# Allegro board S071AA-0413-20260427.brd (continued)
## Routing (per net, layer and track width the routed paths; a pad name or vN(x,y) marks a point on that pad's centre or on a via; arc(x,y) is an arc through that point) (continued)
GND12A_SCG: length 13.7
  L11_DPS w0.076: v2(149.12,210.23) 149.12,210.67 149.92,211.47 156.28,211.47
  L11_DPS w0.203: 156.28,211.47 156.45,211.47 156.66,211.67 v1(160.56,211.67)
  BOTTOM w0.152: SH6.1 160.56,211.68 v1(160.56,211.67)
  vias: v1(120.92,288.29) v1(120.92,283.21) v1(121.7,279.15) v1(129.28,279.15) v1(130.06,288.29) v1(130.06,283.21) v1(141.54,266.67) v1(141.54,263.88) v1(174.34,250.56) v1(174.34,247.77) v1(188.49,214.19) v1(188.49,211.4) v1(191.21,236.22) v1(191.21,233.42)
GND33A_ADC12: length 840.7
  L02_DGND w0.203: K39.6 121.78,141.22 ; K39.6 120.67,140.11 ; K39.6 120.67,142.34 ; K39.6 119.55,141.22 ; 150.03,164.34 K42.6 ; K42.6 151.15,163.22 ; K42.6 151.15,165.46 ; K42.6 152.26,164.34 ; 113.05,140.11 K35.6 ; K35.6 111.93,141.22 ; K35.6 113.05,142.34 ; K35.6 114.16,141.22 ; 128.29,163.22 K41.6 ; K41.6 129.4,164.34 ; K41.6 128.29,165.46 ; K41.6 127.17,164.34 ; K43.7 129.4,153.92 ; K43.7 128.29,155.04 ; K43.7 127.17,153.92 ; K43.7 128.29,152.81 ; K38.7 143.53,178.16 ; K38.7 144.64,177.04 ; K38.7 143.53,175.92 ; K38.7 142.41,177.04 ; K37.6 121.78,164.34 ; K37.6 120.67,163.22 ; K37.6 119.55,164.34 ; K37.6 120.67,165.46 ; 128.29,175.92 K41.7 ; K41.7 128.29,178.16 ; K41.7 129.4,177.04 ; K41.7 127.17,177.04 ; K43.6 129.4,141.22 ; K43.6 128.29,142.34 ; K43.6 128.29,140.11 ; K43.6 127.17,141.22 ; K36.7 135.91,154.79 ; K36.7 137.02,153.67 ; K36.7 135.91,152.55 ; K36.7 134.79,153.67 ; K34.7 135.91,178.16 ; K34.7 134.79,177.04 ; K34.7 137.02,177.04 ; K34.7 135.91,175.92 ; K44.6 151.15,142.09 ; K44.6 151.15,139.85 ; K44.6 152.26,140.97 ; K44.6 150.03,140.97 ; 119.55,177.04 K37.7 ; K37.7 120.67,178.16 ; K37.7 120.67,175.92 ; K37.7 121.78,177.04 ; 150.03,153.67 K44.7 ; K44.7 151.15,154.79 ; K44.7 151.15,152.55 ; K44.7 152.26,153.67 ; 142.41,140.97 K40.6 ; K40.6 144.64,140.97 ; K40.6 143.53,139.85 ; K40.6 143.53,142.09 ; 113.05,163.22 K33.6 ; K33.6 111.93,164.34 ; K33.6 114.16,164.34 ; K33.6 113.05,165.46 ; K42.7 152.26,177.04 ; K42.7 151.15,175.92 ; K42.7 151.15,178.16 ; K42.7 150.03,177.04 ; K33.7 113.05,178.16 ; K33.7 111.93,177.04 ; K33.7 113.05,175.92 ; K33.7 114.16,177.04 ; K35.7 114.16,153.92 ; K35.7 113.05,155.04 ; K35.7 113.05,152.81 ; K35.7 111.93,153.92 ; 119.55,153.92 K39.7 ; K39.7 121.78,153.92 ; K39.7 120.67,155.04 ; K39.7 120.67,152.81 ; 143.53,152.55 K40.7 ; K40.7 142.41,153.67 ; K40.7 144.64,153.67 ; K40.7 143.53,154.79 ; 134.79,164.34 K34.6 ; K34.6 135.91,163.22 ; K34.6 137.02,164.34 ; K34.6 135.91,165.46 ; 143.53,163.22 K38.6 ; K38.6 142.41,164.34 ; K38.6 144.64,164.34 ; K38.6 143.53,165.46 ; 135.91,139.85 K36.6 ; K36.6 135.91,142.09 ; K36.6 137.02,140.97 ; K36.6 134.79,140.97
  L04_DGND w0.203: K33.6 113.05,165.46 ; K33.6 113.05,163.22 ; K33.6 114.16,164.34 ; K33.6 111.93,164.34 ; K39.6 120.67,142.34 ; K39.6 121.78,141.22 ; K39.6 119.55,141.22 ; K39.6 120.67,140.11 ; 128.29,163.22 K41.6 ; K41.6 127.17,164.34 ; K41.6 128.29,165.46 ; K41.6 129.4,164.34 ; 128.29,175.92 K41.7 ; K41.7 129.4,177.04 ; K41.7 127.17,177.04 ; K41.7 128.29,178.16 ; K35.7 113.05,155.04 ; K35.7 111.93,153.92 ; K35.7 114.16,153.92 ; K35.7 113.05,152.81 ; K43.7 128.29,155.04 ; K43.7 127.17,153.92 ; K43.7 129.4,153.92 ; K43.7 128.29,152.81 ; K38.7 143.53,178.16 ; K38.7 142.41,177.04 ; K38.7 143.53,175.92 ; K38.7 144.64,177.04 ; K38.6 144.64,164.34 ; K38.6 143.53,165.46 ; K38.6 142.41,164.34 ; K38.6 143.53,163.22 ; K39.7 121.78,153.92 ; K39.7 120.67,152.81 ; K39.7 119.55,153.92 ; K39.7 120.67,155.04 ; K35.6 113.05,142.34 ; K35.6 111.93,141.22 ; K35.6 113.05,140.11 ; K35.6 114.16,141.22 ; K43.6 129.4,141.22 ; K43.6 127.17,141.22 ; K43.6 128.29,140.11 ; K43.6 128.29,142.34 ; K44.6 152.26,140.97 ; K44.6 151.15,139.85 ; K44.6 150.03,140.97 ; K44.6 151.15,142.09 ; K36.7 135.91,154.79 ; K36.7 137.02,153.67 ; K36.7 134.79,153.67 ; K36.7 135.91,152.55 ; 120.67,175.92 K37.7 ; K37.7 121.78,177.04 ; K37.7 119.55,177.04 ; K37.7 120.67,178.16 ; K44.7 151.15,154.79 ; K44.7 151.15,152.55 ; K44.7 150.03,153.67 ; K44.7 152.26,153.67 ; 142.41,140.97 K40.6 ; K40.6 143.53,139.85 ; K40.6 144.64,140.97 ; K40.6 143.53,142.09 ; 150.03,164.34 K42.6 ; K42.6 151.15,165.46 ; K42.6 151.15,163.22 ; K42.6 152.26,164.34 ; K34.7 137.02,177.04 ; K34.7 134.79,177.04 ; K34.7 135.91,175.92 ; K34.7 135.91,178.16 ; K33.7 113.05,178.16 ; K33.7 113.05,175.92 ; K33.7 114.16,177.04 ; K33.7 111.93,177.04 ; 119.55,164.34 K37.6 ; K37.6 121.78,164.34 ; K37.6 120.67,165.46 ; K37.6 120.67,163.22 ; 135.91,163.22 K34.6 ; K34.6 137.02,164.34 ; K34.6 134.79,164.34 ; K34.6 135.91,165.46 ; K42.7 152.26,177.04 ; K42.7 151.15,178.16 ; K42.7 150.03,177.04 ; K42.7 151.15,175.92 ; K36.6 135.91,142.09 ; K36.6 135.91,139.85 ; K36.6 137.02,140.97 ; K36.6 134.79,140.97 ; 143.53,152.55 K40.7 ; K40.7 142.41,153.67 ; K40.7 144.64,153.67 ; K40.7 143.53,154.79
  L06_DGND w0.203: K44.6 152.26,140.97 ; K44.6 150.03,140.97 ; K44.6 151.15,139.85 ; K44.6 151.15,142.09 ; K34.6 135.91,165.46 ; K34.6 137.02,164.34 ; K34.6 135.91,163.22 ; K34.6 134.79,164.34 ; 120.67,163.22 K37.6 ; K37.6 119.55,164.34 ; K37.6 121.78,164.34 ; K37.6 120.67,165.46 ; K39.6 120.67,142.34 ; K39.6 121.78,141.22 ; K39.6 120.67,140.11 ; K39.6 119.55,141.22 ; K38.6 143.53,165.46 ; K38.6 142.41,164.34 ; K38.6 143.53,163.22 ; K38.6 144.64,164.34 ; K36.7 135.91,154.79 ; K36.7 137.02,153.67 ; K36.7 135.91,152.55 ; K36.7 134.79,153.67 ; 113.05,152.81 K35.7 ; K35.7 114.16,153.92 ; K35.7 111.93,153.92 ; K35.7 113.05,155.04 ; 143.53,152.55 K40.7 ; K40.7 142.41,153.67 ; K40.7 144.64,153.67 ; K40.7 143.53,154.79 ; 128.29,163.22 K41.6 ; K41.6 127.17,164.34 ; K41.6 128.29,165.46 ; K41.6 129.4,164.34 ; K39.7 121.78,153.92 ; K39.7 120.67,155.04 ; K39.7 119.55,153.92 ; K39.7 120.67,152.81 ; K40.6 143.53,142.09 ; K40.6 143.53,139.85 ; K40.6 144.64,140.97 ; K40.6 142.41,140.97 ; K36.6 137.02,140.97 ; K36.6 135.91,139.85 ; K36.6 135.91,142.09 ; K36.6 134.79,140.97 ; K33.6 113.05,165.46 ; K33.6 113.05,163.22 ; K33.6 111.93,164.34 ; K33.6 114.16,164.34 ; K44.7 152.26,153.67 ; K44.7 151.15,154.79 ; K44.7 150.03,153.67 ; K44.7 151.15,152.55 ; 150.03,177.04 K42.7 ; K42.7 151.15,175.92 ; K42.7 151.15,178.16 ; K42.7 152.26,177.04 ; 135.91,175.92 K34.7 ; K34.7 135.91,178.16 ; K34.7 137.02,177.04 ; K34.7 134.79,177.04 ; K35.6 114.16,141.22 ; K35.6 113.05,142.34 ; K35.6 113.05,140.11 ; K35.6 111.93,141.22 ; 127.17,141.22 K43.6 ; K43.6 128.29,140.11 ; K43.6 128.29,142.34 ; K43.6 129.4,141.22 ; K42.6 151.15,165.46 ; K42.6 152.26,164.34 ; K42.6 151.15,163.22 ; K42.6 150.03,164.34 ; K33.7 113.05,178.16 ; K33.7 111.93,177.04 ; K33.7 113.05,175.92 ; K33.7 114.16,177.04 ; K43.7 128.29,155.04 ; K43.7 127.17,153.92 ; K43.7 128.29,152.81 ; K43.7 129.4,153.92 ; 119.55,177.04 K37.7 ; K37.7 120.67,175.92 ; K37.7 121.78,177.04 ; K37.7 120.67,178.16 ; K38.7 144.64,177.04 ; K38.7 143.53,178.16 ; K38.7 143.53,175.92 ; K38.7 142.41,177.04 ; K41.7 129.4,177.04 ; K41.7 127.17,177.04 ; K41.7 128.29,175.92 ; K41.7 128.29,178.16
  L08_DGND w0.203: 143.53,152.55 K40.7 ; K40.7 142.41,153.67 ; K40.7 143.53,154.79 ; K40.7 144.64,153.67 ; 143.53,139.85 K40.6 ; K40.6 143.53,142.09 ; K40.6 144.64,140.97 ; K40.6 142.41,140.97 ; 127.17,141.22 K43.6 ; K43.6 128.29,140.11 ; K43.6 129.4,141.22 ; K43.6 128.29,142.34 ; 135.91,163.22 K34.6 ; K34.6 134.79,164.34 ; K34.6 135.91,165.46 ; K34.6 137.02,164.34 ; 119.55,164.34 K37.6 ; K37.6 120.67,165.46 ; K37.6 120.67,163.22 ; K37.6 121.78,164.34 ; K39.7 120.67,155.04 ; K39.7 120.67,152.81 ; K39.7 119.55,153.92 ; K39.7 121.78,153.92 ; 127.17,153.92 K43.7 ; K43.7 128.29,152.81 ; K43.7 129.4,153.92 ; K43.7 128.29,155.04 ; K35.6 113.05,142.34 ; K35.6 113.05,140.11 ; K35.6 114.16,141.22 ; K35.6 111.93,141.22 ; K34.7 135.91,178.16 ; K34.7 135.91,175.92 ; K34.7 134.79,177.04 ; K34.7 137.02,177.04 ; 143.53,163.22 K38.6 ; K38.6 143.53,165.46 ; K38.6 142.41,164.34 ; K38.6 144.64,164.34 ; K42.7 152.26,177.04 ; K42.7 151.15,175.92 ; K42.7 150.03,177.04 ; K42.7 151.15,178.16 ; K36.6 137.02,140.97 ; K36.6 134.79,140.97 ; K36.6 135.91,142.09 ; K36.6 135.91,139.85 ; K44.7 152.26,153.67 ; K44.7 151.15,154.79 ; K44.7 151.15,152.55 ; K44.7 150.03,153.67 ; K41.7 129.4,177.04 ; K41.7 128.29,178.16 ; K41.7 127.17,177.04 ; K41.7 128.29,175.92 ; 111.93,177.04 K33.7 ; K33.7 113.05,175.92 ; K33.7 113.05,178.16 ; K33.7 114.16,177.04 ; K33.6 113.05,165.46 ; K33.6 111.93,164.34 ; K33.6 114.16,164.34 ; K33.6 113.05,163.22 ; 113.05,152.81 K35.7 ; K35.7 114.16,153.92 ; K35.7 111.93,153.92 ; K35.7 113.05,155.04 ; K37.7 120.67,178.16 ; K37.7 120.67,175.92 ; K37.7 121.78,177.04 ; K37.7 119.55,177.04 ; 143.53,175.92 K38.7 ; K38.7 144.64,177.04 ; K38.7 142.41,177.04 ; K38.7 143.53,178.16 ; 119.55,141.22 K39.6 ; K39.6 121.78,141.22 ; K39.6 120.67,142.34 ; K39.6 120.67,140.11 ; 128.29,163.22 K41.6 ; K41.6 129.4,164.34 ; K41.6 128.29,165.46 ; K41.6 127.17,164.34 ; K44.6 151.15,142.09 ; K44.6 150.03,140.97 ; K44.6 152.26,140.97 ; K44.6 151.15,139.85 ; 135.91,152.55 K36.7 ; K36.7 135.91,154.79 ; K36.7 137.02,153.67 ; K36.7 134.79,153.67 ; K42.6 151.15,165.46 ; K42.6 150.03,164.34 ; K42.6 152.26,164.34 ; K42.6 151.15,163.22
  L10_DGND w0.203: 151.15,175.92 K42.7 ; K42.7 151.15,178.16 ; K42.7 150.03,177.04 ; K42.7 152.26,177.04 ; 143.53,175.92 K38.7 ; K38.7 143.53,178.16 ; K38.7 142.41,177.04 ; K38.7 144.64,177.04
  L11_DPS w0.076: v2(145.92,207.03) 145.92,206.68
  L11_DPS w0.203: 145.92,206.68 145.92,206.3 148.13,204.1 v1(148.13,200.22)
  L12_DGND w0.203: K42.7 151.15,178.16 ; K42.7 150.03,177.04 ; K42.7 152.26,177.04 ; K42.7 151.15,175.92 ; 142.41,177.04 K38.7 ; K38.7 143.53,178.16 ; K38.7 143.53,175.92 ; K38.7 144.64,177.04
  L17_DGND w0.203: 150.03,140.97 K44.6 ; K44.6 152.26,140.97 ; K44.6 151.15,142.09 ; K44.6 151.15,139.85 ; 111.93,141.22 K35.6 ; K35.6 114.16,141.22 ; K35.6 113.05,142.34 ; K35.6 113.05,140.11 ; 135.91,175.92 K34.7 ; K34.7 137.02,177.04 ; K34.7 134.79,177.04 ; K34.7 135.91,178.16 ; 143.53,175.92 K38.7 ; K38.7 142.41,177.04 ; K38.7 144.64,177.04 ; K38.7 143.53,178.16 ; K40.7 144.64,153.67 ; K40.7 142.41,153.67 ; K40.7 143.53,152.55 ; K40.7 143.53,154.79 ; 151.15,152.55 K44.7 ; K44.7 152.26,153.67 ; K44.7 150.03,153.67 ; K44.7 151.15,154.79 ; K33.6 114.16,164.34 ; K33.6 111.93,164.34 ; K33.6 113.05,165.46 ; K33.6 113.05,163.22 ; K39.6 120.67,142.34 ; K39.6 121.78,141.22 ; K39.6 119.55,141.22 ; K39.6 120.67,140.11 ; 111.93,153.92 K35.7 ; K35.7 113.05,155.04 ; K35.7 114.16,153.92 ; K35.7 113.05,152.81 ; K34.6 135.91,165.46 ; K34.6 137.02,164.34 ; K34.6 134.79,164.34 ; K34.6 135.91,163.22 ; 120.67,152.81 K39.7 ; K39.7 121.78,153.92 ; K39.7 120.67,155.04 ; K39.7 119.55,153.92 ; K40.6 143.53,142.09 ; K40.6 143.53,139.85 ; K40.6 144.64,140.97 ; K40.6 142.41,140.97 ; K38.6 144.64,164.34 ; K38.6 143.53,163.22 ; K38.6 142.41,164.34 ; K38.6 143.53,165.46 ; 127.17,177.04 K41.7 ; K41.7 128.29,178.16 ; K41.7 129.4,177.04 ; K41.7 128.29,175.92 ; K36.7 135.91,154.79 ; K36.7 137.02,153.67 ; K36.7 134.79,153.67 ; K36.7 135.91,152.55 ; K43.7 129.4,153.92 ; K43.7 128.29,152.81 ; K43.7 128.29,155.04 ; K43.7 127.17,153.92 ; 128.29,163.22 K41.6 ; K41.6 129.4,164.34 ; K41.6 128.29,165.46 ; K41.6 127.17,164.34 ; 113.05,175.92 K33.7 ; K33.7 114.16,177.04 ; K33.7 111.93,177.04 ; K33.7 113.05,178.16 ; 151.15,175.92 K42.7 ; K42.7 150.03,177.04 ; K42.7 152.26,177.04 ; K42.7 151.15,178.16 ; K37.6 120.67,165.46 ; K37.6 119.55,164.34 ; K37.6 120.67,163.22 ; K37.6 121.78,164.34 ; 150.03,164.34 K42.6 ; K42.6 151.15,165.46 ; K42.6 151.15,163.22 ; K42.6 152.26,164.34 ; K43.6 129.4,141.22 ; K43.6 128.29,142.34 ; K43.6 128.29,140.11 ; K43.6 127.17,141.22 ; 120.67,175.92 K37.7 ; K37.7 119.55,177.04 ; K37.7 121.78,177.04 ; K37.7 120.67,178.16 ; K36.6 135.91,142.09 ; K36.6 134.79,140.97 ; K36.6 137.02,140.97 ; K36.6 135.91,139.85
  L19_DGND w0.203: 135.91,139.85 K36.6 ; K36.6 137.02,140.97 ; K36.6 135.91,142.09 ; K36.6 134.79,140.97 ; 143.53,175.92 K38.7 ; K38.7 142.41,177.04 ; K38.7 144.64,177.04 ; K38.7 143.53,178.16 ; 151.15,175.92 K42.7 ; K42.7 150.03,177.04 ; K42.7 152.26,177.04 ; K42.7 151.15,178.16 ; 150.03,164.34 K42.6 ; K42.6 152.26,164.34 ; K42.6 151.15,163.22 ; K42.6 151.15,165.46 ; 120.67,152.81 K39.7 ; K39.7 120.67,155.04 ; K39.7 119.55,153.92 ; K39.7 121.78,153.92 ; K35.6 114.16,141.22 ; K35.6 113.05,140.11 ; K35.6 111.93,141.22 ; K35.6 113.05,142.34 ; 111.93,177.04 K33.7 ; K33.7 113.05,178.16 ; K33.7 113.05,175.92 ; K33.7 114.16,177.04 ; K43.6 129.4,141.22 ; K43.6 128.29,140.11 ; K43.6 128.29,142.34 ; K43.6 127.17,141.22 ; K38.6 143.53,165.46 ; K38.6 142.41,164.34 ; K38.6 144.64,164.34 ; K38.6 143.53,163.22 ; K34.6 135.91,165.46 ; K34.6 135.91,163.22 ; K34.6 137.02,164.34 ; K34.6 134.79,164.34 ; K37.7 121.78,177.04 ; K37.7 120.67,175.92 ; K37.7 119.55,177.04 ; K37.7 120.67,178.16 ; K44.6 152.26,140.97 ; K44.6 150.03,140.97 ; K44.6 151.15,139.85 ; K44.6 151.15,142.09 ; 127.17,153.92 K43.7 ; K43.7 129.4,153.92 ; K43.7 128.29,152.81 ; K43.7 128.29,155.04 ; K41.7 128.29,178.16 ; K41.7 129.4,177.04 ; K41.7 127.17,177.04 ; K41.7 128.29,175.92 ; 151.15,152.55 K44.7 ; K44.7 150.03,153.67 ; K44.7 151.15,154.79 ; K44.7 152.26,153.67 ; K41.6 129.4,164.34 ; K41.6 128.29,165.46 ; K41.6 127.17,164.34 ; K41.6 128.29,163.22 ; 113.05,152.81 K35.7 ; K35.7 114.16,153.92 ; K35.7 113.05,155.04 ; K35.7 111.93,153.92 ; K34.7 135.91,178.16 ; K34.7 135.91,175.92 ; K34.7 137.02,177.04 ; K34.7 134.79,177.04 ; 119.55,164.34 K37.6 ; K37.6 121.78,164.34 ; K37.6 120.67,165.46 ; K37.6 120.67,163.22 ; 142.41,140.97 K40.6 ; K40.6 143.53,142.09 ; K40.6 144.64,140.97 ; K40.6 143.53,139.85 ; K40.7 143.53,154.79 ; K40.7 144.64,153.67 ; K40.7 142.41,153.67 ; K40.7 143.53,152.55 ; K33.6 113.05,165.46 ; K33.6 113.05,163.22 ; K33.6 114.16,164.34 ; K33.6 111.93,164.34 ; K36.7 137.02,153.67 ; K36.7 134.79,153.67 ; K36.7 135.91,154.79 ; K36.7 135.91,152.55 ; 120.67,140.11 K39.6 ; K39.6 121.78,141.22 ; K39.6 120.67,142.34 ; K39.6 119.55,141.22
  L23_DGND w0.203: K37.6 120.67,165.46 ; K37.6 121.78,164.34 ; K37.6 120.67,163.22 ; K37.6 119.55,164.34 ; 127.17,164.34 K41.6 ; K41.6 129.4,164.34 ; K41.6 128.29,165.46 ; K41.6 128.29,163.22 ; 113.05,175.92 K33.7 ; K33.7 113.05,178.16 ; K33.7 111.93,177.04 ; K33.7 114.16,177.04 ; K39.6 120.67,142.34 ; K39.6 120.67,140.11 ; K39.6 121.78,141.22 ; K39.6 119.55,141.22 ; 150.03,153.67 K44.7 ; K44.7 151.15,154.79 ; K44.7 152.26,153.67 ; K44.7 151.15,152.55 ; K39.7 120.67,155.04 ; K39.7 120.67,152.81 ; K39.7 119.55,153.92 ; K39.7 121.78,153.92 ; K40.6 144.64,140.97 ; K40.6 142.41,140.97 ; K40.6 143.53,139.85 ; K40.6 143.53,142.09 ; 128.29,140.11 K43.6 ; K43.6 128.29,142.34 ; K43.6 127.17,141.22 ; K43.6 129.4,141.22 ; 113.05,163.22 K33.6 ; K33.6 113.05,165.46 ; K33.6 111.93,164.34 ; K33.6 114.16,164.34 ; K36.7 137.02,153.67 ; K36.7 135.91,154.79 ; K36.7 134.79,153.67 ; K36.7 135.91,152.55 ; K36.6 137.02,140.97 ; K36.6 135.91,142.09 ; K36.6 134.79,140.97 ; K36.6 135.91,139.85 ; 111.93,153.92 K35.7 ; K35.7 113.05,152.81 ; K35.7 113.05,155.04 ; K35.7 114.16,153.92 ; K38.6 143.53,165.46 ; K38.6 144.64,164.34 ; K38.6 143.53,163.22 ; K38.6 142.41,164.34 ; K35.6 113.05,142.34 ; K35.6 114.16,141.22 ; K35.6 113.05,140.11 ; K35.6 111.93,141.22 ; K43.7 129.4,153.92 ; K43.7 128.29,152.81 ; K43.7 127.17,153.92 ; K43.7 128.29,155.04 ; 135.91,163.22 K34.6 ; K34.6 134.79,164.34 ; K34.6 135.91,165.46 ; K34.6 137.02,164.34 ; 142.41,153.67 K40.7 ; K40.7 144.64,153.67 ; K40.7 143.53,152.55 ; K40.7 143.53,154.79 ; 150.03,140.97 K44.6 ; K44.6 151.15,139.85 ; K44.6 152.26,140.97 ; K44.6 151.15,142.09 ; K42.6 152.26,164.34 ; K42.6 150.03,164.34 ; K42.6 151.15,163.22 ; K42.6 151.15,165.46
  L25_DGND w0.203: 150.03,164.34 K42.6 ; K42.6 151.15,163.22 ; K42.6 151.15,165.46 ; K42.6 152.26,164.34 ; 143.53,163.22 K38.6 ; K38.6 143.53,165.46 ; K38.6 144.64,164.34 ; K38.6 142.41,164.34 ; 135.91,163.22 K34.6 ; K34.6 137.02,164.34 ; K34.6 134.79,164.34 ; K34.6 135.91,165.46 ; K41.6 129.4,164.34 ; K41.6 127.17,164.34 ; K41.6 128.29,165.46 ; K41.6 128.29,163.22 ; 135.91,139.85 K36.6 ; K36.6 135.91,142.09 ; K36.6 137.02,140.97 ; K36.6 134.79,140.97 ; K39.7 120.67,155.04 ; K39.7 119.55,153.92 ; K39.7 120.67,152.81 ; K39.7 121.78,153.92 ; K36.7 135.91,154.79 ; K36.7 134.79,153.67 ; K36.7 135.91,152.55 ; K36.7 137.02,153.67 ; 151.15,152.55 K44.7 ; K44.7 151.15,154.79 ; K44.7 152.26,153.67 ; K44.7 150.03,153.67 ; 142.41,140.97 K40.6 ; K40.6 143.53,139.85 ; K40.6 144.64,140.97 ; K40.6 143.53,142.09 ; 151.15,139.85 K44.6 ; K44.6 150.03,140.97 ; K44.6 152.26,140.97 ; K44.6 151.15,142.09 ; 120.67,163.22 K37.6 ; K37.6 119.55,164.34 ; K37.6 121.78,164.34 ; K37.6 120.67,165.46 ; 119.55,141.22 K39.6 ; K39.6 120.67,142.34 ; K39.6 120.67,140.11 ; K39.6 121.78,141.22 ; K35.7 114.16,153.92 ; K35.7 113.05,155.04 ; K35.7 111.93,153.92 ; K35.7 113.05,152.81 ; K33.6 114.16,164.34 ; K33.6 113.05,165.46 ; K33.6 113.05,163.22 ; K33.6 111.93,164.34 ; 113.05,175.92 K33.7 ; K33.7 113.05,178.16 ; K33.7 111.93,177.04 ; K33.7 114.16,177.04 ; 127.17,153.92 K43.7 ; K43.7 128.29,152.81 ; K43.7 128.29,155.04 ; K43.7 129.4,153.92 ; 128.29,140.11 K43.6 ; K43.6 129.4,141.22 ; K43.6 127.17,141.22 ; K43.6 128.29,142.34 ; 111.93,141.22 K35.6 ; K35.6 114.16,141.22 ; K35.6 113.05,140.11 ; K35.6 113.05,142.34 ; 143.53,152.55 K40.7 ; K40.7 143.53,154.79 ; K40.7 144.64,153.67 ; K40.7 142.41,153.67
  BOTTOM w0.152: SH8.1 v1(148.13,200.22)
  vias: v1(131.72,148.32) v1(136.8,188.96) v1(143.78,288.29) v1(143.78,283.21) v1(144.56,279.15) v1(146.96,148.32) v1(152.14,279.15) v1(152.92,288.29) v1(152.92,283.21) v1(157.12,148.32) v1(161.24,175.22) v1(161.24,172.43) v1(162.2,158.48) v1(162.2,153.4) v1(162.2,148.32) v1(162.2,143.24) v1(162.2,138.16) v1(167.28,153.4) v1(167.28,148.32) v1(167.28,143.24) v1(167.28,138.16) v1(172.36,148.32) v1(172.36,143.24) v1(172.36,138.16) v1(177.44,143.24) v1(177.44,138.16) v1(182.52,138.16) v1(187.65,179.08) v1(187.65,176.29) v1(232.14,210.8) v1(232.14,208.01) v1(232.44,270.37) v1(232.44,267.57) v2(142.72,207.83) v2(142.72,207.03) v2(143.52,210.23) v2(145.92,210.23) v2(145.92,209.43) v2(145.92,208.63) v2(145.92,207.83) v2(146.72,212.63) v2(146.78,211.84)
GND33A_ADC32: length 2740.1
  L02_DGND w0.203: K12.7 92.32,204.72 ; K12.7 91.2,205.84 ; K12.7 91.2,203.61 ; K12.7 90.08,204.72 ; 78.5,195.99 K10.6 ; K10.6 77.38,197.1 ; K10.6 78.5,198.22 ; K10.6 79.62,197.1 ; K32.7 115.94,242.82 ; K32.7 113.71,242.82 ; K32.7 114.82,241.71 ; K6.6 31.26,198.22 ; K6.6 30.14,197.1 ; K6.6 31.26,195.99 ; K6.6 32.38,197.1 ; 113.71,227.58 K24.7 ; K24.7 114.82,228.7 ; K24.7 115.94,227.58 ; K24.7 114.82,226.47 ; K5.6 32.38,204.72 ; K5.6 31.26,203.61 ; K5.6 31.26,205.84 ; K5.6 30.14,204.72 ; K20.6 103.24,219.96 ; K20.6 102.12,221.08 ; K20.6 102.12,218.85 ; K20.6 101.01,219.96 ; K16.7 43.96,190.6 ; K16.7 43.96,188.37 ; K16.7 45.08,189.48 ; K16.7 42.84,189.48 ; 42.84,242.82 K29.7 ; K29.7 45.08,242.82 ; K29.7 43.96,241.71 ; K2.6 79.62,189.48 ; K2.6 77.38,189.48 ; K2.6 78.5,188.37 ; K2.6 78.5,190.6 ; K21.7 43.96,228.7 ; K21.7 45.08,227.58 ; K21.7 42.84,227.58 ; K21.7 43.96,226.47 ; 31.26,226.47 K21.6 ; K21.6 31.26,228.7 ; K21.6 30.14,227.58 ; K21.6 32.38,227.58 ; 67.58,241.71 K30.7 ; K30.7 66.46,242.82 ; K30.7 68.7,242.82 ; K15.6 103.24,212.34 ; K15.6 101.01,212.34 ; K15.6 102.12,211.23 ; K15.6 102.12,213.46 ; K10.7 92.32,197.1 ; K10.7 91.2,195.99 ; K10.7 90.08,197.1 ; K10.7 91.2,198.22 ; K6.7 43.96,198.22 ; K6.7 42.84,197.1 ; K6.7 45.08,197.1 ; K6.7 43.96,195.99 ; K28.6 102.12,236.32 ; K28.6 101.01,235.2 ; K28.6 103.24,235.2 ; K28.6 102.12,234.09 ; 78.5,226.47 K23.6 ; K23.6 77.38,227.58 ; K23.6 78.5,228.7 ; K23.6 79.62,227.58 ; K15.7 115.94,212.34 ; K15.7 114.82,213.46 ; K15.7 114.82,211.23 ; K15.7 113.71,212.34 ; K11.7 115.94,197.1 ; K11.7 114.82,195.99 ; K11.7 113.71,197.1 ; K11.7 114.82,198.22 ; K20.7 115.94,219.96 ; K20.7 114.82,218.85 ; K20.7 114.82,221.08 ; K20.7 113.71,219.96 ; 42.84,235.2 K25.7 ; K25.7 43.96,234.09 ; K25.7 43.96,236.32 ; K25.7 45.08,235.2 ; 42.84,204.72 K5.7 ; K5.7 43.96,203.61 ; K5.7 43.96,205.84 ; K5.7 45.08,204.72 ; 30.14,219.96 K17.6 ; K17.6 31.26,218.85 ; K17.6 31.26,221.08 ; K17.6 32.38,219.96 ; K2.7 91.2,190.6 ; K2.7 91.2,188.37 ; K2.7 90.08,189.48 ; K2.7 92.32,189.48 ; K8.7 67.58,205.84 ; K8.7 68.7,204.72 ; K8.7 67.58,203.61 ; K8.7 66.46,204.72 ; 30.14,212.34 K4.6 ; K4.6 31.26,211.23 ; K4.6 32.38,212.34 ; K4.6 31.26,213.46 ; 113.71,235.2 K28.7 ; K28.7 114.82,236.32 ; K28.7 115.94,235.2 ; K28.7 114.82,234.09 ; 78.5,211.23 K14.6 ; K14.6 77.38,212.34 ; K14.6 79.62,212.34 ; K14.6 78.5,213.46 ; K26.7 67.58,236.32 ; K26.7 67.58,234.09 ; K26.7 66.46,235.2 ; K26.7 68.7,235.2 ; K11.6 102.12,198.22 ; K11.6 102.12,195.99 ; K11.6 101.01,197.1 ; K11.6 103.24,197.1 ; K1.6 102.12,190.6 ; K1.6 102.12,188.37 ; K1.6 101.01,189.48 ; K1.6 103.24,189.48 ; 91.2,241.71 K31.7 ; K31.7 92.32,242.82 ; K31.7 90.08,242.82 ; 53.76,242.82 K30.6 ; K30.6 54.88,241.71 ; K30.6 56,242.82 ; 54.88,203.61 K8.6 ; K8.6 54.88,205.84 ; K8.6 53.76,204.72 ; K8.6 56,204.72 ; K19.7 92.32,219.96 ; K19.7 90.08,219.96 ; K19.7 91.2,221.08 ; K19.7 91.2,218.85 ; K27.7 91.2,236.32 ; K27.7 90.08,235.2 ; K27.7 91.2,234.09 ; K27.7 92.32,235.2 ; 67.58,226.47 K22.7 ; K22.7 68.7,227.58 ; K22.7 66.46,227.58 ; K22.7 67.58,228.7 ; 31.26,241.71 K29.6 ; K29.6 30.14,242.82 ; K29.6 32.38,242.82 ; 90.08,212.34 K14.7 ; K14.7 92.32,212.34 ; K14.7 91.2,213.46 ; K14.7 91.2,211.23 ; K9.7 68.7,197.1 ; K9.7 66.46,197.1 ; K9.7 67.58,195.99 ; K9.7 67.58,198.22 ; K22.6 56,227.58 ; K22.6 54.88,226.47 ; K22.6 53.76,227.58 ; K22.6 54.88,228.7 ; 67.58,188.37 K3.7 ; K3.7 67.58,190.6 ; K3.7 68.7,189.48 ; K3.7 66.46,189.48 ; K24.6 102.12,228.7 ; K24.6 101.01,227.58 ; K24.6 103.24,227.58 ; K24.6 102.12,226.47 ; 67.58,211.23 K7.7 ; K7.7 67.58,213.46 ; K7.7 68.7,212.34 ; K7.7 66.46,212.34 ; 30.14,235.2 K25.6 ; K25.6 32.38,235.2 ; K25.6 31.26,236.32 ; K25.6 31.26,234.09 ; 78.5,234.09 K27.6 ; K27.6 78.5,236.32 ; K27.6 79.62,235.2 ; K27.6 77.38,235.2 ; 78.5,203.61 K12.6 ; K12.6 78.5,205.84 ; K12.6 79.62,204.72 ; K12.6 77.38,204.72 ; K26.6 54.88,236.32 ; K26.6 56,235.2 ; K26.6 54.88,234.09 ; K26.6 53.76,235.2 ; K3.6 56,189.48 ; K3.6 54.88,190.6 ; K3.6 54.88,188.37 ; K3.6 53.76,189.48 ; 31.26,188.37 K16.6 ; K16.6 31.26,190.6 ; K16.6 32.38,189.48 ; K16.6 30.14,189.48 ; 77.38,219.96 K19.6 ; K19.6 78.5,218.85 ; K19.6 78.5,221.08 ; K19.6 79.62,219.96 ; 67.58,218.85 K18.7 ; K18.7 66.46,219.96 ; K18.7 67.58,221.08 ; K18.7 68.7,219.96 ; 102.12,203.61 K13.6 ; K13.6 102.12,205.84 ; K13.6 103.24,204.72 ; K13.6 101.01,204.72 ; K17.7 45.08,219.96 ; K17.7 43.96,218.85 ; K17.7 42.84,219.96 ; K17.7 43.96,221.08 ; 42.84,212.34 K4.7 ; K4.7 43.96,211.23 ; K4.7 45.08,212.34 ; K4.7 43.96,213.46 ; 54.88,195.99 K9.6 ; K9.6 56,197.1 ; K9.6 53.76,197.1 ; K9.6 54.88,198.22 ; K23.7 92.32,227.58 ; K23.7 91.2,228.7 ; K23.7 91.2,226.47 ; K23.7 90.08,227.58 ; K7.6 56,212.34 ; K7.6 54.88,213.46 ; K7.6 54.88,211.23 ; K7.6 53.76,212.34 ; K13.7 114.82,205.84 ; K13.7 114.82,203.61 ; K13.7 115.94,204.72 ; K13.7 113.71,204.72 ; K32.6 103.24,242.82 ; K32.6 101.01,242.82 ; K32.6 102.12,241.71 ; 114.82,188.37 K1.7 ; K1.7 113.71,189.48 ; K1.7 115.94,189.48 ; K1.7 114.82,190.6 ; K18.6 54.88,221.08 ; K18.6 56,219.96 ; K18.6 54.88,218.85 ; K18.6 53.76,219.96 ; 77.38,242.82 K31.6 ; K31.6 79.62,242.82 ; K31.6 78.5,241.71
  L04_DGND w0.203: K15.6 103.24,212.34 ; K15.6 102.12,211.23 ; K15.6 102.12,213.46 ; K15.6 101.01,212.34 ; K10.7 91.2,198.22 ; K10.7 91.2,195.99 ; K10.7 92.32,197.1 ; K10.7 90.08,197.1 ; K4.6 31.26,213.46 ; K4.6 30.14,212.34 ; K4.6 31.26,211.23 ; K4.6 32.38,212.34 ; 30.14,219.96 K17.6 ; K17.6 31.26,221.08 ; K17.6 32.38,219.96 ; K17.6 31.26,218.85 ; 91.2,226.47 K23.7 ; K23.7 91.2,228.7 ; K23.7 90.08,227.58 ; K23.7 92.32,227.58 ; 66.46,219.96 K18.7 ; K18.7 67.58,221.08 ; K18.7 67.58,218.85 ; K18.7 68.7,219.96 ; K9.7 68.7,197.1 ; K9.7 66.46,197.1 ; K9.7 67.58,198.22 ; K9.7 67.58,195.99 ; 101.01,204.72 K13.6 ; K13.6 103.24,204.72 ; K13.6 102.12,205.84 ; K13.6 102.12,203.61 ; K20.7 114.82,221.08 ; K20.7 113.71,219.96 ; K20.7 114.82,218.85 ; K20.7 115.94,219.96 ; 53.76,235.2 K26.6 ; K26.6 56,235.2 ; K26.6 54.88,234.09 ; K26.6 54.88,236.32 ; 114.82,226.47 K24.7 ; K24.7 115.94,227.58 ; K24.7 113.71,227.58 ; K24.7 114.82,228.7 ; 90.08,219.96 K19.7 ; K19.7 92.32,219.96 ; K19.7 91.2,221.08 ; K19.7 91.2,218.85 ; K7.7 67.58,213.46 ; K7.7 68.7,212.34 ; K7.7 66.46,212.34 ; K7.7 67.58,211.23 ; 113.71,235.2 K28.7 ; K28.7 115.94,235.2 ; K28.7 114.82,236.32 ; K28.7 114.82,234.09 ; 43.96,218.85 K17.7 ; K17.7 43.96,221.08 ; K17.7 42.84,219.96 ; K17.7 45.08,219.96 ; K8.6 54.88,205.84 ; K8.6 53.76,204.72 ; K8.6 56,204.72 ; K8.6 54.88,203.61 ; K23.6 78.5,228.7 ; K23.6 78.5,226.47 ; K23.6 79.62,227.58 ; K23.6 77.38,227.58 ; 66.46,189.48 K3.7 ; K3.7 68.7,189.48 ; K3.7 67.58,190.6 ; K3.7 67.58,188.37 ; 67.58,226.47 K22.7 ; K22.7 67.58,228.7 ; K22.7 68.7,227.58 ; K22.7 66.46,227.58 ; 53.76,242.82 K30.6 ; K30.6 56,242.82 ; K30.6 54.88,241.71 ; K5.7 45.08,204.72 ; K5.7 42.84,204.72 ; K5.7 43.96,205.84 ; K5.7 43.96,203.61 ; 101.01,242.82 K32.6 ; K32.6 103.24,242.82 ; K32.6 102.12,241.71 ; K22.6 56,227.58 ; K22.6 54.88,228.7 ; K22.6 54.88,226.47 ; K22.6 53.76,227.58 ; 78.5,234.09 K27.6 ; K27.6 77.38,235.2 ; K27.6 79.62,235.2 ; K27.6 78.5,236.32 ; K16.7 45.08,189.48 ; K16.7 43.96,188.37 ; K16.7 42.84,189.48 ; K16.7 43.96,190.6 ; K15.7 115.94,212.34 ; K15.7 114.82,213.46 ; K15.7 113.71,212.34 ; K15.7 114.82,211.23 ; K25.6 31.26,236.32 ; K25.6 31.26,234.09 ; K25.6 32.38,235.2 ; K25.6 30.14,235.2 ; 31.26,188.37 K16.6 ; K16.6 32.38,189.48 ; K16.6 31.26,190.6 ; K16.6 30.14,189.48 ; K27.7 92.32,235.2 ; K27.7 91.2,234.09 ; K27.7 91.2,236.32 ; K27.7 90.08,235.2 ; 113.71,189.48 K1.7 ; K1.7 114.82,190.6 ; K1.7 115.94,189.48 ; K1.7 114.82,188.37 ; K11.7 114.82,198.22 ; K11.7 114.82,195.99 ; K11.7 113.71,197.1 ; K11.7 115.94,197.1 ; 101.01,219.96 K20.6 ; K20.6 102.12,218.85 ; K20.6 102.12,221.08 ; K20.6 103.24,219.96 ; 77.38,197.1 K10.6 ; K10.6 78.5,195.99 ; K10.6 78.5,198.22 ; K10.6 79.62,197.1 ; 78.5,203.61 K12.6 ; K12.6 77.38,204.72 ; K12.6 79.62,204.72 ; K12.6 78.5,205.84 ; K6.7 45.08,197.1 ; K6.7 43.96,195.99 ; K6.7 42.84,197.1 ; K6.7 43.96,198.22 ; 66.46,204.72 K8.7 ; K8.7 67.58,205.84 ; K8.7 67.58,203.61 ; K8.7 68.7,204.72 ; 77.38,189.48 K2.6 ; K2.6 79.62,189.48 ; K2.6 78.5,188.37 ; K2.6 78.5,190.6 ; K7.6 56,212.34 ; K7.6 54.88,211.23 ; K7.6 53.76,212.34 ; K7.6 54.88,213.46 ; 31.26,195.99 K6.6 ; K6.6 31.26,198.22 ; K6.6 30.14,197.1 ; K6.6 32.38,197.1 ; K11.6 102.12,198.22 ; K11.6 102.12,195.99 ; K11.6 101.01,197.1 ; K11.6 103.24,197.1 ; 101.01,227.58 K24.6 ; K24.6 102.12,228.7 ; K24.6 102.12,226.47 ; K24.6 103.24,227.58 ; K26.7 67.58,236.32 ; K26.7 67.58,234.09 ; K26.7 66.46,235.2 ; K26.7 68.7,235.2 ; K29.7 45.08,242.82 ; K29.7 42.84,242.82 ; K29.7 43.96,241.71 ; K28.6 102.12,236.32 ; K28.6 101.01,235.2 ; K28.6 103.24,235.2 ; K28.6 102.12,234.09 ; K18.6 56,219.96 ; K18.6 54.88,221.08 ; K18.6 54.88,218.85 ; K18.6 53.76,219.96 ; K5.6 31.26,205.84 ; K5.6 32.38,204.72 ; K5.6 31.26,203.61 ; K5.6 30.14,204.72 ; 78.5,241.71 K31.6 ; K31.6 77.38,242.82 ; K31.6 79.62,242.82 ; K4.7 45.08,212.34 ; K4.7 42.84,212.34 ; K4.7 43.96,213.46 ; K4.7 43.96,211.23 ; 91.2,241.71 K31.7 ; K31.7 90.08,242.82 ; K31.7 92.32,242.82 ; K2.7 92.32,189.48 ; K2.7 91.2,188.37 ; K2.7 90.08,189.48 ; K2.7 91.2,190.6 ; 30.14,227.58 K21.6 ; K21.6 31.26,226.47 ; K21.6 31.26,228.7 ; K21.6 32.38,227.58 ; K14.6 79.62,212.34 ; K14.6 77.38,212.34 ; K14.6 78.5,213.46 ; K14.6 78.5,211.23 ; 54.88,195.99 K9.6 ; K9.6 54.88,198.22 ; K9.6 53.76,197.1 ; K9.6 56,197.1 ; K29.6 32.38,242.82 ; K29.6 31.26,241.71 ; K29.6 30.14,242.82 ; K19.6 78.5,221.08 ; K19.6 79.62,219.96 ; K19.6 78.5,218.85 ; K19.6 77.38,219.96 ; K1.6 102.12,190.6 ; K1.6 103.24,189.48 ; K1.6 101.01,189.48 ; K1.6 102.12,188.37 ; 54.88,188.37 K3.6 ; K3.6 56,189.48 ; K3.6 54.88,190.6 ; K3.6 53.76,189.48 ; 114.82,241.71 K32.7 ; K32.7 113.71,242.82 ; K32.7 115.94,242.82 ; 67.58,241.71 K30.7 ; K30.7 68.7,242.82 ; K30.7 66.46,242.82 ; 91.2,203.61 K12.7 ; K12.7 90.08,204.72 ; K12.7 92.32,204.72 ; K12.7 91.2,205.84 ; K14.7 92.32,212.34 ; K14.7 90.08,212.34 ; K14.7 91.2,213.46 ; K14.7 91.2,211.23 ; 43.96,226.47 K21.7 ; K21.7 45.08,227.58 ; K21.7 43.96,228.7 ; K21.7 42.84,227.58 ; 43.96,234.09 K25.7 ; K25.7 43.96,236.32 ; K25.7 42.84,235.2 ; K25.7 45.08,235.2 ; K13.7 114.82,205.84 ; K13.7 113.71,204.72 ; K13.7 115.94,204.72 ; K13.7 114.82,203.61
  L06_DGND w0.203: 113.71,227.58 K24.7 ; K24.7 114.82,226.47 ; K24.7 114.82,228.7 ; K24.7 115.94,227.58 ; 66.46,219.96 K18.7 ; K18.7 67.58,218.85 ; K18.7 68.7,219.96 ; K18.7 67.58,221.08 ; 30.14,242.82 K29.6 ; K29.6 32.38,242.82 ; K29.6 31.26,241.71 ; 43.96,211.23 K4.7 ; K4.7 43.96,213.46 ; K4.7 45.08,212.34 ; K4.7 42.84,212.34 ; K25.7 45.08,235.2 ; K25.7 43.96,234.09 ; K25.7 42.84,235.2 ; K25.7 43.96,236.32 ; K2.6 78.5,190.6 ; K2.6 79.62,189.48 ; K2.6 78.5,188.37 ; K2.6 77.38,189.48 ; 77.38,242.82 K31.6 ; K31.6 78.5,241.71 ; K31.6 79.62,242.82 ; K23.7 92.32,227.58 ; K23.7 91.2,228.7 ; K23.7 90.08,227.58 ; K23.7 91.2,226.47 ; K32.6 103.24,242.82 ; K32.6 101.01,242.82 ; K32.6 102.12,241.71 ; 53.76,227.58 K22.6 ; K22.6 54.88,226.47 ; K22.6 54.88,228.7 ; K22.6 56,227.58 ; 102.12,226.47 K24.6 ; K24.6 102.12,228.7 ; K24.6 103.24,227.58 ; K24.6 101.01,227.58 ; 101.01,235.2 K28.6 ; K28.6 102.12,234.09 ; K28.6 102.12,236.32 ; K28.6 103.24,235.2 ; K16.6 31.26,190.6 ; K16.6 32.38,189.48 ; K16.6 30.14,189.48 ; K16.6 31.26,188.37 ; K16.7 43.96,190.6 ; K16.7 45.08,189.48 ; K16.7 43.96,188.37 ; K16.7 42.84,189.48 ; 90.08,219.96 K19.7 ; K19.7 91.2,218.85 ; K19.7 91.2,221.08 ; K19.7 92.32,219.96 ; 113.71,204.72 K13.7 ; K13.7 114.82,205.84 ; K13.7 115.94,204.72 ; K13.7 114.82,203.61 ; K21.7 45.08,227.58 ; K21.7 43.96,226.47 ; K21.7 42.84,227.58 ; K21.7 43.96,228.7 ; K26.6 56,235.2 ; K26.6 54.88,236.32 ; K26.6 54.88,234.09 ; K26.6 53.76,235.2 ; 53.76,204.72 K8.6 ; K8.6 56,204.72 ; K8.6 54.88,203.61 ; K8.6 54.88,205.84 ; 66.46,242.82 K30.7 ; K30.7 67.58,241.71 ; K30.7 68.7,242.82 ; K7.6 54.88,213.46 ; K7.6 54.88,211.23 ; K7.6 56,212.34 ; K7.6 53.76,212.34 ; 101.01,219.96 K20.6 ; K20.6 102.12,221.08 ; K20.6 102.12,218.85 ; K20.6 103.24,219.96 ; K3.7 67.58,190.6 ; K3.7 66.46,189.48 ; K3.7 68.7,189.48 ; K3.7 67.58,188.37 ; K7.7 67.58,213.46 ; K7.7 67.58,211.23 ; K7.7 66.46,212.34 ; K7.7 68.7,212.34 ; 90.08,197.1 K10.7 ; K10.7 91.2,195.99 ; K10.7 91.2,198.22 ; K10.7 92.32,197.1 ; K12.7 92.32,204.72 ; K12.7 90.08,204.72 ; K12.7 91.2,203.61 ; K12.7 91.2,205.84 ; 43.96,203.61 K5.7 ; K5.7 42.84,204.72 ; K5.7 43.96,205.84 ; K5.7 45.08,204.72 ; K1.7 115.94,189.48 ; K1.7 114.82,188.37 ; K1.7 113.71,189.48 ; K1.7 114.82,190.6 ; 54.88,241.71 K30.6 ; K30.6 56,242.82 ; K30.6 53.76,242.82 ; 67.58,234.09 K26.7 ; K26.7 68.7,235.2 ; K26.7 67.58,236.32 ; K26.7 66.46,235.2 ; 54.88,218.85 K18.6 ; K18.6 54.88,221.08 ; K18.6 53.76,219.96 ; K18.6 56,219.96 ; 30.14,227.58 K21.6 ; K21.6 31.26,228.7 ; K21.6 31.26,226.47 ; K21.6 32.38,227.58 ; K8.7 67.58,205.84 ; K8.7 68.7,204.72 ; K8.7 66.46,204.72 ; K8.7 67.58,203.61 ; K9.6 56,197.1 ; K9.6 53.76,197.1 ; K9.6 54.88,198.22 ; K9.6 54.88,195.99 ; K25.6 32.38,235.2 ; K25.6 30.14,235.2 ; K25.6 31.26,234.09 ; K25.6 31.26,236.32 ; K9.7 67.58,198.22 ; K9.7 68.7,197.1 ; K9.7 66.46,197.1 ; K9.7 67.58,195.99 ; K10.6 78.5,198.22 ; K10.6 79.62,197.1 ; K10.6 77.38,197.1 ; K10.6 78.5,195.99 ; K14.7 92.32,212.34 ; K14.7 91.2,211.23 ; K14.7 90.08,212.34 ; K14.7 91.2,213.46 ; K29.7 45.08,242.82 ; K29.7 43.96,241.71 ; K29.7 42.84,242.82 ; 77.38,219.96 K19.6 ; K19.6 78.5,218.85 ; K19.6 78.5,221.08 ; K19.6 79.62,219.96 ; 30.14,212.34 K4.6 ; K4.6 32.38,212.34 ; K4.6 31.26,211.23 ; K4.6 31.26,213.46 ; 113.71,242.82 K32.7 ; K32.7 115.94,242.82 ; K32.7 114.82,241.71 ; K27.6 78.5,236.32 ; K27.6 77.38,235.2 ; K27.6 79.62,235.2 ; K27.6 78.5,234.09 ; K17.7 45.08,219.96 ; K17.7 43.96,221.08 ; K17.7 42.84,219.96 ; K17.7 43.96,218.85 ; 90.08,235.2 K27.7 ; K27.7 91.2,236.32 ; K27.7 92.32,235.2 ; K27.7 91.2,234.09 ; 77.38,212.34 K14.6 ; K14.6 78.5,211.23 ; K14.6 79.62,212.34 ; K14.6 78.5,213.46 ; 102.12,211.23 K15.6 ; K15.6 102.12,213.46 ; K15.6 103.24,212.34 ; K15.6 101.01,212.34 ; K2.7 91.2,190.6 ; K2.7 91.2,188.37 ; K2.7 92.32,189.48 ; K2.7 90.08,189.48 ; 113.71,197.1 K11.7 ; K11.7 115.94,197.1 ; K11.7 114.82,198.22 ; K11.7 114.82,195.99 ; 113.71,235.2 K28.7 ; K28.7 115.94,235.2 ; K28.7 114.82,234.09 ; K28.7 114.82,236.32 ; 101.01,189.48 K1.6 ; K1.6 102.12,188.37 ; K1.6 102.12,190.6 ; K1.6 103.24,189.48 ; K11.6 102.12,198.22 ; K11.6 101.01,197.1 ; K11.6 102.12,195.99 ; K11.6 103.24,197.1 ; 54.88,188.37 K3.6 ; K3.6 53.76,189.48 ; K3.6 56,189.48 ; K3.6 54.88,190.6 ; K17.6 32.38,219.96 ; K17.6 30.14,219.96 ; K17.6 31.26,218.85 ; K17.6 31.26,221.08 ; 30.14,197.1 K6.6 ; K6.6 31.26,195.99 ; K6.6 32.38,197.1 ; K6.6 31.26,198.22 ; K23.6 79.62,227.58 ; K23.6 77.38,227.58 ; K23.6 78.5,226.47 ; K23.6 78.5,228.7 ; K5.6 31.26,205.84 ; K5.6 31.26,203.61 ; K5.6 32.38,204.72 ; K5.6 30.14,204.72 ; K15.7 114.82,213.46 ; K15.7 113.71,212.34 ; K15.7 115.94,212.34 ; K15.7 114.82,211.23 ; K12.6 78.5,205.84 ; K12.6 77.38,204.72 ; K12.6 79.62,204.72 ; K12.6 78.5,203.61 ; K13.6 102.12,205.84 ; K13.6 102.12,203.61 ; K13.6 103.24,204.72 ; K13.6 101.01,204.72 ; 91.2,241.71 K31.7 ; K31.7 90.08,242.82 ; K31.7 92.32,242.82 ; K20.7 115.94,219.96 ; K20.7 114.82,218.85 ; K20.7 113.71,219.96 ; K20.7 114.82,221.08 ; K22.7 67.58,228.7 ; K22.7 68.7,227.58 ; K22.7 66.46,227.58 ; K22.7 67.58,226.47 ; K6.7 43.96,198.22 ; K6.7 42.84,197.1 ; K6.7 43.96,195.99 ; K6.7 45.08,197.1
  L08_DGND w0.203: K23.7 91.2,228.7 ; K23.7 90.08,227.58 ; K23.7 91.2,226.47 ; K23.7 92.32,227.58 ; 78.5,211.23 K14.6 ; K14.6 77.38,212.34 ; K14.6 79.62,212.34 ; K14.6 78.5,213.46 ; 31.26,241.71 K29.6 ; K29.6 30.14,242.82 ; K29.6 32.38,242.82 ; K14.7 91.2,213.46 ; K14.7 90.08,212.34 ; K14.7 92.32,212.34 ; K14.7 91.2,211.23 ; K5.7 45.08,204.72 ; K5.7 42.84,204.72 ; K5.7 43.96,205.84 ; K5.7 43.96,203.61 ; K7.6 54.88,213.46 ; K7.6 56,212.34 ; K7.6 54.88,211.23 ; K7.6 53.76,212.34 ; K4.7 45.08,212.34 ; K4.7 42.84,212.34 ; K4.7 43.96,213.46 ; K4.7 43.96,211.23 ; K24.6 102.12,228.7 ; K24.6 101.01,227.58 ; K24.6 102.12,226.47 ; K24.6 103.24,227.58 ; 78.5,226.47 K23.6 ; K23.6 78.5,228.7 ; K23.6 77.38,227.58 ; K23.6 79.62,227.58 ; 114.82,211.23 K15.7 ; K15.7 114.82,213.46 ; K15.7 113.71,212.34 ; K15.7 115.94,212.34 ; K26.6 56,235.2 ; K26.6 53.76,235.2 ; K26.6 54.88,234.09 ; K26.6 54.88,236.32 ; 102.12,218.85 K20.6 ; K20.6 103.24,219.96 ; K20.6 102.12,221.08 ; K20.6 101.01,219.96 ; 113.71,197.1 K11.7 ; K11.7 114.82,195.99 ; K11.7 114.82,198.22 ; K11.7 115.94,197.1 ; K18.6 56,219.96 ; K18.6 54.88,218.85 ; K18.6 54.88,221.08 ; K18.6 53.76,219.96 ; K7.7 68.7,212.34 ; K7.7 66.46,212.34 ; K7.7 67.58,213.46 ; K7.7 67.58,211.23 ; 78.5,203.61 K12.6 ; K12.6 77.38,204.72 ; K12.6 78.5,205.84 ; K12.6 79.62,204.72 ; K32.6 102.12,243.94 ; K32.6 101.01,242.82 ; K32.6 102.12,241.71 ; K32.6 103.24,242.82 ; K5.6 32.38,204.72 ; K5.6 30.14,204.72 ; K5.6 31.26,205.84 ; K5.6 31.26,203.61 ; K27.6 79.62,235.2 ; K27.6 78.5,236.32 ; K27.6 77.38,235.2 ; K27.6 78.5,234.09 ; K13.6 102.12,205.84 ; K13.6 102.12,203.61 ; K13.6 103.24,204.72 ; K13.6 101.01,204.72 ; 78.5,218.85 K19.6 ; K19.6 77.38,219.96 ; K19.6 78.5,221.08 ; K19.6 79.62,219.96 ; 91.2,218.85 K19.7 ; K19.7 92.32,219.96 ; K19.7 90.08,219.96 ; K19.7 91.2,221.08 ; K25.7 43.96,236.32 ; K25.7 43.96,234.09 ; K25.7 45.08,235.2 ; K25.7 42.84,235.2 ; K12.7 91.2,205.84 ; K12.7 90.08,204.72 ; K12.7 91.2,203.61 ; K12.7 92.32,204.72 ; K3.7 67.58,190.6 ; K3.7 67.58,188.37 ; K3.7 68.7,189.48 ; K3.7 66.46,189.48 ; 54.88,241.71 K30.6 ; K30.6 54.88,243.94 ; K30.6 56,242.82 ; K30.6 53.76,242.82 ; K22.7 67.58,228.7 ; K22.7 66.46,227.58 ; K22.7 68.7,227.58 ; K22.7 67.58,226.47 ; K30.7 68.7,242.82 ; K30.7 66.46,242.82 ; K30.7 67.58,243.94 ; K30.7 67.58,241.71 ; K15.6 102.12,213.46 ; K15.6 102.12,211.23 ; K15.6 101.01,212.34 ; K15.6 103.24,212.34 ; 90.08,242.82 K31.7 ; K31.7 91.2,241.71 ; K31.7 91.2,243.94 ; K31.7 92.32,242.82 ; 113.71,235.2 K28.7 ; K28.7 115.94,235.2 ; K28.7 114.82,234.09 ; K28.7 114.82,236.32 ; K9.7 67.58,198.22 ; K9.7 66.46,197.1 ; K9.7 68.7,197.1 ; K9.7 67.58,195.99 ; K2.7 91.2,190.6 ; K2.7 91.2,188.37 ; K2.7 92.32,189.48 ; K2.7 90.08,189.48 ; K10.7 91.2,198.22 ; K10.7 90.08,197.1 ; K10.7 91.2,195.99 ; K10.7 92.32,197.1 ; 30.14,219.96 K17.6 ; K17.6 31.26,218.85 ; K17.6 32.38,219.96 ; K17.6 31.26,221.08 ; 114.82,226.47 K24.7 ; K24.7 115.94,227.58 ; K24.7 114.82,228.7 ; K24.7 113.71,227.58 ; 30.14,235.2 K25.6 ; K25.6 32.38,235.2 ; K25.6 31.26,234.09 ; K25.6 31.26,236.32 ; 54.88,188.37 K3.6 ; K3.6 56,189.48 ; K3.6 53.76,189.48 ; K3.6 54.88,190.6 ; 77.38,242.82 K31.6 ; K31.6 78.5,243.94 ; K31.6 78.5,241.71 ; K31.6 79.62,242.82 ; 113.71,219.96 K20.7 ; K20.7 115.94,219.96 ; K20.7 114.82,218.85 ; K20.7 114.82,221.08 ; 53.76,227.58 K22.6 ; K22.6 54.88,228.7 ; K22.6 54.88,226.47 ; K22.6 56,227.58 ; 102.12,188.37 K1.6 ; K1.6 103.24,189.48 ; K1.6 101.01,189.48 ; K1.6 102.12,190.6 ; 30.14,197.1 K6.6 ; K6.6 31.26,195.99 ; K6.6 32.38,197.1 ; K6.6 31.26,198.22 ; K28.6 103.24,235.2 ; K28.6 102.12,234.09 ; K28.6 102.12,236.32 ; K28.6 101.01,235.2 ; K10.6 79.62,197.1 ; K10.6 78.5,195.99 ; K10.6 77.38,197.1 ; K10.6 78.5,198.22 ; K1.7 114.82,190.6 ; K1.7 114.82,188.37 ; K1.7 115.94,189.48 ; K1.7 113.71,189.48 ; 66.46,235.2 K26.7 ; K26.7 68.7,235.2 ; K26.7 67.58,236.32 ; K26.7 67.58,234.09 ; K21.7 45.08,227.58 ; K21.7 43.96,226.47 ; K21.7 42.84,227.58 ; K21.7 43.96,228.7 ; K8.6 56,204.72 ; K8.6 54.88,203.61 ; K8.6 53.76,204.72 ; K8.6 54.88,205.84 ; 78.5,188.37 K2.6 ; K2.6 78.5,190.6 ; K2.6 77.38,189.48 ; K2.6 79.62,189.48 ; 54.88,195.99 K9.6 ; K9.6 54.88,198.22 ; K9.6 53.76,197.1 ; K9.6 56,197.1 ; K17.7 45.08,219.96 ; K17.7 43.96,221.08 ; K17.7 42.84,219.96 ; K17.7 43.96,218.85 ; 30.14,227.58 K21.6 ; K21.6 32.38,227.58 ; K21.6 31.26,228.7 ; K21.6 31.26,226.47 ; K4.6 31.26,213.46 ; K4.6 32.38,212.34 ; K4.6 31.26,211.23 ; K4.6 30.14,212.34 ; 30.14,189.48 K16.6 ; K16.6 32.38,189.48 ; K16.6 31.26,188.37 ; K16.6 31.26,190.6 ; 114.82,241.71 K32.7 ; K32.7 115.94,242.82 ; K32.7 113.71,242.82 ; K32.7 114.82,243.94 ; K13.7 114.82,205.84 ; K13.7 115.94,204.72 ; K13.7 113.71,204.72 ; K13.7 114.82,203.61 ; 67.58,218.85 K18.7 ; K18.7 67.58,221.08 ; K18.7 68.7,219.96 ; K18.7 66.46,219.96 ; K6.7 45.08,197.1 ; K6.7 42.84,197.1 ; K6.7 43.96,198.22 ; K6.7 43.96,195.99 ; 90.08,235.2 K27.7 ; K27.7 91.2,234.09 ; K27.7 92.32,235.2 ; K27.7 91.2,236.32 ; K11.6 102.12,198.22 ; K11.6 101.01,197.1 ; K11.6 102.12,195.99 ; K11.6 103.24,197.1 ; 42.84,189.48 K16.7 ; K16.7 45.08,189.48 ; K16.7 43.96,188.37 ; K16.7 43.96,190.6 ; K29.7 43.96,243.94 ; K29.7 45.08,242.82 ; K29.7 42.84,242.82 ; K29.7 43.96,241.71 ; 66.46,204.72 K8.7 ; K8.7 67.58,205.84 ; K8.7 68.7,204.72 ; K8.7 67.58,203.61
  L09_DPS w0.076: 138.29,213.06 v2(138.72,212.63)
  L09_DPS w0.203: 138.29,213.06 137.84,213.51 v1(132.52,213.51)
  L10_DGND w0.203: 54.88,218.85 K18.6 ; K18.6 56,219.96 ; K18.6 54.88,221.08 ; K18.6 53.76,219.96 ; 101.01,227.58 K24.6 ; K24.6 102.12,226.47 ; K24.6 103.24,227.58 ; K24.6 102.12,228.7 ; 77.38,219.96 K19.6 ; K19.6 78.5,221.08 ; K19.6 79.62,219.96 ; K19.6 78.5,218.85 ; K20.7 115.94,219.96 ; K20.7 114.82,221.08 ; K20.7 114.82,218.85 ; K20.7 113.71,219.96 ; 67.58,241.71 K30.7 ; K30.7 67.58,243.94 ; K30.7 66.46,242.82 ; K30.7 68.7,242.82 ; 54.88,211.23 K7.6 ; K7.6 56,212.34 ; K7.6 54.88,213.46 ; K7.6 53.76,212.34 ; K28.7 115.94,235.2 ; K28.7 113.71,235.2 ; K28.7 114.82,236.32 ; K28.7 114.82,234.09 ; K14.7 92.32,212.34 ; K14.7 91.2,211.23 ; K14.7 91.2,213.46 ; K14.7 90.08,212.34 ; K13.7 115.94,204.72 ; K13.7 114.82,205.84 ; K13.7 114.82,203.61 ; K13.7 113.71,204.72 ; 43.96,234.09 K25.7 ; K25.7 43.96,236.32 ; K25.7 45.08,235.2 ; 78.5,203.61 K12.6 ; K12.6 77.38,204.72 ; K12.6 78.5,205.84 ; K12.6 79.62,204.72 ; 78.5,226.47 K23.6 ; K23.6 77.38,227.58 ; K23.6 78.5,228.7 ; K23.6 79.62,227.58 ; K13.6 103.24,204.72 ; K13.6 101.01,204.72 ; K13.6 102.12,205.84 ; K13.6 102.12,203.61 ; 114.82,226.47 K24.7 ; K24.7 113.71,227.58 ; K24.7 114.82,228.7 ; K24.7 115.94,227.58 ; K22.6 56,227.58 ; K22.6 53.76,227.58 ; K22.6 54.88,226.47 ; K22.6 54.88,228.7 ; 56,204.72 K8.6 54.88,205.84 ; 66.46,212.34 K7.7 ; K7.7 67.58,211.23 ; K7.7 67.58,213.46 ; K7.7 68.7,212.34 ; K23.7 91.2,228.7 ; K23.7 91.2,226.47 ; K23.7 90.08,227.58 ; K23.7 92.32,227.58 ; 54.88,234.09 K26.6 ; K26.6 54.88,236.32 ; K26.6 53.76,235.2 ; K26.6 56,235.2 ; K31.6 79.62,242.82 ; K31.6 78.5,241.71 ; K31.6 77.38,242.82 ; K31.6 78.5,243.94 ; 113.71,212.34 K15.7 ; K15.7 114.82,213.46 ; K15.7 114.82,211.23 ; K15.7 115.94,212.34 ; 102.12,211.23 K15.6 ; K15.6 102.12,213.46 ; K15.6 103.24,212.34 ; K15.6 101.01,212.34 ; K31.7 91.2,243.94 ; K31.7 91.2,241.71 ; K31.7 92.32,242.82 ; K31.7 90.08,242.82 ; K14.6 78.5,213.46 ; K14.6 77.38,212.34 ; K14.6 79.62,212.34 ; K14.6 78.5,211.23 ; K18.7 67.58,221.08 ; K18.7 66.46,219.96 ; K18.7 67.58,218.85 ; K18.7 68.7,219.96 ; 114.82,241.71 K32.7 ; K32.7 113.71,242.82 ; K32.7 114.82,243.94 ; K32.7 115.94,242.82 ; 90.08,235.2 K27.7 ; K27.7 91.2,234.09 ; K27.7 92.32,235.2 ; K27.7 91.2,236.32 ; 66.46,204.72 K8.7 ; K8.7 67.58,205.84 ; K8.7 67.58,203.61 ; K8.7 68.7,204.72 ; 101.01,219.96 K20.6 ; K20.6 102.12,218.85 ; K20.6 102.12,221.08 ; K20.6 103.24,219.96 ; K12.7 92.32,204.72 ; K12.7 91.2,203.61 ; K12.7 90.08,204.72 ; K12.7 91.2,205.84 ; 102.12,234.09 K28.6 ; K28.6 102.12,236.32 ; K28.6 101.01,235.2 ; K28.6 103.24,235.2 ; 90.08,219.96 K19.7 ; K19.7 92.32,219.96 ; K19.7 91.2,221.08 ; K19.7 91.2,218.85 ; 67.58,226.47 K22.7 ; K22.7 68.7,227.58 ; K22.7 67.58,228.7 ; K22.7 66.46,227.58 ; K32.6 103.24,242.82 ; K32.6 102.12,241.71 ; K32.6 101.01,242.82 ; K32.6 102.12,243.94 ; K29.7 43.96,243.94 ; K29.7 43.96,241.71 ; K29.7 45.08,242.82 ; 43.96,226.47 K21.7 ; K21.7 45.08,227.58 ; K21.7 43.96,228.7 ; 77.38,235.2 K27.6 ; K27.6 78.5,234.09 ; K27.6 79.62,235.2 ; K27.6 78.5,236.32 ; 67.58,234.09 K26.7 ; K26.7 67.58,236.32 ; K26.7 66.46,235.2 ; K26.7 68.7,235.2 ; K17.7 43.96,221.08 ; K17.7 43.96,218.85 ; K17.7 45.08,219.96 ; 53.76,242.82 K30.6 ; K30.6 54.88,241.71 ; K30.6 56,242.82 ; K30.6 54.88,243.94
  L15_DGND w0.203: 31.26,218.85 K17.6 ; K17.6 31.26,221.08 ; K17.6 30.14,219.96 ; K17.6 32.38,219.96 ; K5.7 43.96,205.84 ; K5.7 43.96,203.61 ; K5.7 45.08,204.72 ; K5.7 42.84,204.72 ; 31.26,241.71 K29.6 ; K29.6 31.26,243.94 ; K29.6 32.38,242.82 ; K29.6 30.14,242.82 ; K6.7 43.96,198.22 ; K6.7 45.08,197.1 ; K6.7 43.96,195.99 ; K6.7 42.84,197.1 ; K5.6 31.26,205.84 ; K5.6 32.38,204.72 ; K5.6 30.14,204.72 ; K5.6 31.26,203.61 ; 43.96,234.09 K25.7 ; K25.7 43.96,236.32 ; K25.7 42.84,235.2 ; K25.7 45.08,235.2 ; K21.6 31.26,228.7 ; K21.6 31.26,226.47 ; K21.6 32.38,227.58 ; K21.6 30.14,227.58 ; K21.7 45.08,227.58 ; K21.7 42.84,227.58 ; K21.7 43.96,226.47 ; K21.7 43.96,228.7 ; K3.6 54.88,190.6 ; K3.6 53.76,189.48 ; K3.6 56,189.48 ; K3.6 54.88,188.37 ; 53.76,227.58 K22.6 ; K22.6 56,227.58 ; K22.6 54.88,226.47 ; K22.6 54.88,228.7 ; 42.84,242.82 K29.7 ; K29.7 43.96,243.94 ; K29.7 43.96,241.71 ; K29.7 45.08,242.82 ; K17.7 43.96,221.08 ; K17.7 43.96,218.85 ; K17.7 45.08,219.96 ; K17.7 42.84,219.96 ; K18.6 54.88,221.08 ; K18.6 54.88,218.85 ; K18.6 53.76,219.96 ; K18.6 56,219.96 ; K4.6 32.38,212.34 ; K4.6 31.26,213.46 ; K4.6 30.14,212.34 ; K4.6 31.26,211.23 ; 53.76,197.1 K9.6 ; K9.6 54.88,198.22 ; K9.6 56,197.1 ; K9.6 54.88,195.99 ; 43.96,188.37 K16.7 ; K16.7 42.84,189.48 ; K16.7 43.96,190.6 ; K16.7 45.08,189.48 ; K16.6 31.26,190.6 ; K16.6 31.26,188.37 ; K16.6 30.14,189.48 ; K16.6 32.38,189.48 ; 30.14,197.1 K6.6 ; K6.6 32.38,197.1 ; K6.6 31.26,198.22 ; K6.6 31.26,195.99 ; 54.88,203.61 K8.6 ; K8.6 53.76,204.72 ; K8.6 56,204.72 ; K8.6 54.88,205.84 ; K4.7 43.96,213.46 ; K4.7 45.08,212.34 ; K4.7 42.84,212.34 ; K4.7 43.96,211.23 ; K25.6 31.26,236.32 ; K25.6 32.38,235.2 ; K25.6 30.14,235.2 ; K25.6 31.26,234.09 ; 53.76,235.2 K26.6 ; K26.6 54.88,236.32 ; K26.6 56,235.2 ; K26.6 54.88,234.09 ; K30.6 56,242.82 ; K30.6 54.88,243.94 ; K30.6 53.76,242.82 ; K30.6 54.88,241.71 ; 54.88,211.23 K7.6 ; K7.6 56,212.34 ; K7.6 53.76,212.34 ; K7.6 54.88,213.46
  L17_DGND w0.203: 91.2,218.85 K19.7 ; K19.7 90.08,219.96 ; K19.7 92.32,219.96 ; K19.7 91.2,221.08 ; K18.6 54.88,221.08 ; K18.6 53.76,219.96 ; K18.6 54.88,218.85 ; K18.6 56,219.96 ; 78.5,211.23 K14.6 ; K14.6 79.62,212.34 ; K14.6 78.5,213.46 ; K14.6 77.38,212.34 ; 54.88,188.37 K3.6 ; K3.6 56,189.48 ; K3.6 54.88,190.6 ; K3.6 53.76,189.48 ; K4.7 43.96,213.46 ; K4.7 45.08,212.34 ; K4.7 43.96,211.23 ; K4.7 42.84,212.34 ; K1.7 115.94,189.48 ; K1.7 113.71,189.48 ; K1.7 114.82,190.6 ; K1.7 114.82,188.37 ; 53.76,212.34 K7.6 ; K7.6 56,212.34 ; K7.6 54.88,213.46 ; K7.6 54.88,211.23 ; K22.6 54.88,228.7 ; K22.6 56,227.58 ; K22.6 54.88,226.47 ; K22.6 53.76,227.58 ; K17.6 32.38,219.96 ; K17.6 31.26,218.85 ; K17.6 30.14,219.96 ; K17.6 31.26,221.08 ; 42.84,227.58 K21.7 ; K21.7 45.08,227.58 ; K21.7 43.96,226.47 ; K21.7 43.96,228.7 ; K28.6 103.24,235.2 ; K28.6 102.12,236.32 ; K28.6 101.01,235.2 ; K28.6 102.12,234.09 ; K25.6 31.26,236.32 ; K25.6 32.38,235.2 ; K25.6 31.26,234.09 ; K25.6 30.14,235.2 ; K15.6 102.12,213.46 ; K15.6 103.24,212.34 ; K15.6 102.12,211.23 ; K15.6 101.01,212.34 ; 66.46,212.34 K7.7 ; K7.7 67.58,213.46 ; K7.7 68.7,212.34 ; K7.7 67.58,211.23 ; 54.88,234.09 K26.6 ; K26.6 54.88,236.32 ; K26.6 53.76,235.2 ; K26.6 56,235.2 ; K17.7 45.08,219.96 ; K17.7 43.96,221.08 ; K17.7 42.84,219.96 ; K17.7 43.96,218.85 ; 114.82,203.61 K13.7 ; K13.7 113.71,204.72 ; K13.7 114.82,205.84 ; K13.7 115.94,204.72 ; K9.7 68.7,197.1 ; K9.7 66.46,197.1 ; K9.7 67.58,195.99 ; K9.7 67.58,198.22 ; K9.6 54.88,198.22 ; K9.6 54.88,195.99 ; K9.6 56,197.1 ; K9.6 53.76,197.1 ; 54.88,241.71 K30.6 ; K30.6 54.88,243.94 ; K30.6 56,242.82 ; K30.6 53.76,242.82 ; 67.58,241.71 K30.7 ; K30.7 66.46,242.82 ; K30.7 68.7,242.82 ; 101.01,227.58 K24.6 ; K24.6 102.12,228.7 ; K24.6 103.24,227.58 ; K24.6 102.12,226.47 ; 91.2,211.23 K14.7 ; K14.7 91.2,213.46 ; K14.7 90.08,212.34 ; K14.7 92.32,212.34 ; 90.08,235.2 K27.7 ; K27.7 91.2,234.09 ; K27.7 92.32,235.2 ; K27.7 91.2,236.32 ; 77.38,197.1 K10.6 ; K10.6 79.62,197.1 ; K10.6 78.5,195.99 ; K10.6 78.5,198.22 ; 67.58,226.47 K22.7 ; K22.7 67.58,228.7 ; K22.7 68.7,227.58 ; K22.7 66.46,227.58 ; K5.6 31.26,205.84 ; K5.6 32.38,204.72 ; K5.6 31.26,203.61 ; K5.6 30.14,204.72 ; K6.6 31.26,198.22 ; K6.6 31.26,195.99 ; K6.6 30.14,197.1 ; K6.6 32.38,197.1 ; 113.71,235.2 K28.7 ; K28.7 114.82,236.32 ; K28.7 115.94,235.2 ; K28.7 114.82,234.09 ; K20.6 102.12,221.08 ; K20.6 103.24,219.96 ; K20.6 101.01,219.96 ; K20.6 102.12,218.85 ; K21.6 31.26,228.7 ; K21.6 32.38,227.58 ; K21.6 31.26,226.47 ; K21.6 30.14,227.58 ; K18.7 68.7,219.96 ; K18.7 67.58,218.85 ; K18.7 67.58,221.08 ; K18.7 66.46,219.96 ; K32.6 103.24,242.82 ; K32.6 102.12,241.71 ; K32.6 101.01,242.82 ; K25.7 43.96,236.32 ; K25.7 42.84,235.2 ; K25.7 43.96,234.09 ; K25.7 45.08,235.2 ; 67.58,234.09 K26.7 ; K26.7 67.58,236.32 ; K26.7 66.46,235.2 ; K26.7 68.7,235.2 ; 30.14,189.48 K16.6 ; K16.6 31.26,190.6 ; K16.6 31.26,188.37 ; K16.6 32.38,189.48 ; 113.71,219.96 K20.7 ; K20.7 114.82,218.85 ; K20.7 114.82,221.08 ; K20.7 115.94,219.96 ; 113.71,242.82 K32.7 ; K32.7 114.82,241.71 ; K32.7 115.94,242.82 ; K4.6 32.38,212.34 ; K4.6 31.26,211.23 ; K4.6 30.14,212.34 ; K4.6 31.26,213.46 ; K29.6 32.38,242.82 ; K29.6 30.14,242.82 ; K29.6 31.26,243.94 ; K29.6 31.26,241.71 ; K5.7 45.08,204.72 ; K5.7 42.84,204.72 ; K5.7 43.96,203.61 ; K5.7 43.96,205.84 ; 77.38,227.58 K23.6 ; K23.6 78.5,228.7 ; K23.6 78.5,226.47 ; K23.6 79.62,227.58 ; K15.7 114.82,213.46 ; K15.7 113.71,212.34 ; K15.7 114.82,211.23 ; K15.7 115.94,212.34 ; 42.84,242.82 K29.7 ; K29.7 43.96,243.94 ; K29.7 45.08,242.82 ; K29.7 43.96,241.71 ; K23.7 91.2,228.7 ; K23.7 92.32,227.58 ; K23.7 91.2,226.47 ; K23.7 90.08,227.58 ; K10.7 92.32,197.1 ; K10.7 91.2,198.22 ; K10.7 90.08,197.1 ; K10.7 91.2,195.99 ; 101.01,197.1 K11.6 ; K11.6 102.12,195.99 ; K11.6 102.12,198.22 ; K11.6 103.24,197.1 ; 113.71,197.1 K11.7 ; K11.7 114.82,195.99 ; K11.7 114.82,198.22 ; K11.7 115.94,197.1 ; K12.6 78.5,205.84 ; K12.6 79.62,204.72 ; K12.6 78.5,203.61 ; K12.6 77.38,204.72 ; K19.6 79.62,219.96 ; K19.6 77.38,219.96 ; K19.6 78.5,218.85 ; K19.6 78.5,221.08 ; K2.6 79.62,189.48 ; K2.6 77.38,189.48 ; K2.6 78.5,190.6 ; K2.6 78.5,188.37 ; K8.6 56,204.72 ; K8.6 53.76,204.72 ; K8.6 54.88,203.61 ; K8.6 54.88,205.84 ; K13.6 103.24,204.72 ; K13.6 102.12,203.61 ; K13.6 101.01,204.72 ; K13.6 102.12,205.84 ; K27.6 78.5,236.32 ; K27.6 79.62,235.2 ; K27.6 78.5,234.09 ; K27.6 77.38,235.2 ; 77.38,242.82 K31.6 ; K31.6 78.5,241.71 ; K31.6 79.62,242.82 ; 43.96,195.99 K6.7 ; K6.7 42.84,197.1 ; K6.7 43.96,198.22 ; K6.7 45.08,197.1 ; K12.7 92.32,204.72 ; K12.7 91.2,205.84 ; K12.7 90.08,204.72 ; K12.7 91.2,203.61 ; K24.7 115.94,227.58 ; K24.7 114.82,226.47 ; K24.7 114.82,228.7 ; K24.7 113.71,227.58 ; K3.7 68.7,189.48 ; K3.7 66.46,189.48 ; K3.7 67.58,190.6 ; K3.7 67.58,188.37 ; K8.7 67.58,205.84 ; K8.7 66.46,204.72 ; K8.7 68.7,204.72 ; K8.7 67.58,203.61 ; 102.12,188.37 K1.6 ; K1.6 101.01,189.48 ; K1.6 103.24,189.48 ; K1.6 102.12,190.6 ; 91.2,241.71 K31.7 ; K31.7 92.32,242.82 ; K31.7 90.08,242.82 ; 43.96,188.37 K16.7 ; K16.7 45.08,189.48 ; K16.7 42.84,189.48 ; K16.7 43.96,190.6 ; 90.08,189.48 K2.7 ; K2.7 92.32,189.48 ; K2.7 91.2,190.6 ; K2.7 91.2,188.37
  L19_DGND w0.203: K1.7 115.94,189.48 ; K1.7 114.82,188.37 ; K1.7 113.71,189.48 ; K1.7 114.82,190.6 ; 101.01,242.82 K32.6 ; K32.6 102.12,241.71 ; K32.6 103.24,242.82 ; K22.6 54.88,228.7 ; K22.6 56,227.58 ; K22.6 54.88,226.47 ; K22.6 53.76,227.58 ; K14.6 78.5,213.46 ; K14.6 78.5,211.23 ; K14.6 77.38,212.34 ; K14.6 79.62,212.34 ; 113.71,197.1 K11.7 ; K11.7 114.82,195.99 ; K11.7 115.94,197.1 ; K11.7 114.82,198.22 ; K24.6 102.12,228.7 ; K24.6 102.12,226.47 ; K24.6 101.01,227.58 ; K24.6 103.24,227.58 ; 31.26,188.37 K16.6 ; K16.6 32.38,189.48 ; K16.6 30.14,189.48 ; K16.6 31.26,190.6 ; 30.14,197.1 K6.6 ; K6.6 32.38,197.1 ; K6.6 31.26,198.22 ; K6.6 31.26,195.99 ; K12.7 91.2,205.84 ; K12.7 90.08,204.72 ; K12.7 92.32,204.72 ; K12.7 91.2,203.61 ; K27.7 92.32,235.2 ; K27.7 90.08,235.2 ; K27.7 91.2,234.09 ; K27.7 91.2,236.32 ; 114.82,226.47 K24.7 ; K24.7 115.94,227.58 ; K24.7 113.71,227.58 ; K24.7 114.82,228.7 ; 101.01,219.96 K20.6 ; K20.6 103.24,219.96 ; K20.6 102.12,221.08 ; K20.6 102.12,218.85 ; K28.6 102.12,236.32 ; K28.6 103.24,235.2 ; K28.6 101.01,235.2 ; K28.6 102.12,234.09 ; K15.7 114.82,213.46 ; K15.7 113.71,212.34 ; K15.7 114.82,211.23 ; K15.7 115.94,212.34 ; 30.14,219.96 K17.6 ; K17.6 31.26,221.08 ; K17.6 32.38,219.96 ; K17.6 31.26,218.85 ; 67.58,218.85 K18.7 ; K18.7 68.7,219.96 ; K18.7 67.58,221.08 ; K18.7 66.46,219.96 ; 78.5,218.85 K19.6 ; K19.6 79.62,219.96 ; K19.6 77.38,219.96 ; K19.6 78.5,221.08 ; 43.96,203.61 K5.7 ; K5.7 43.96,205.84 ; K5.7 45.08,204.72 ; K5.7 42.84,204.72 ; K6.7 45.08,197.1 ; K6.7 43.96,198.22 ; K6.7 43.96,195.99 ; K6.7 42.84,197.1 ; K1.6 103.24,189.48 ; K1.6 102.12,190.6 ; K1.6 102.12,188.37 ; K1.6 101.01,189.48 ; K21.7 45.08,227.58 ; K21.7 43.96,226.47 ; K21.7 43.96,228.7 ; K21.7 42.84,227.58 ; K15.6 102.12,213.46 ; K15.6 103.24,212.34 ; K15.6 101.01,212.34 ; K15.6 102.12,211.23 ; 102.12,195.99 K11.6 ; K11.6 103.24,197.1 ; K11.6 101.01,197.1 ; K11.6 102.12,198.22 ; 30.14,235.2 K25.6 ; K25.6 32.38,235.2 ; K25.6 31.26,234.09 ; K25.6 31.26,236.32 ; K23.7 91.2,228.7 ; K23.7 92.32,227.58 ; K23.7 91.2,226.47 ; K23.7 90.08,227.58 ; K8.7 68.7,204.72 ; K8.7 66.46,204.72 ; K8.7 67.58,203.61 ; K8.7 67.58,205.84 ; 114.82,218.85 K20.7 ; K20.7 114.82,221.08 ; K20.7 115.94,219.96 ; K20.7 113.71,219.96 ; K18.6 54.88,221.08 ; K18.6 56,219.96 ; K18.6 53.76,219.96 ; K18.6 54.88,218.85 ; 54.88,241.71 K30.6 ; K30.6 53.76,242.82 ; K30.6 56,242.82 ; 42.84,189.48 K16.7 ; K16.7 43.96,188.37 ; K16.7 45.08,189.48 ; K16.7 43.96,190.6 ; K5.6 32.38,204.72 ; K5.6 31.26,203.61 ; K5.6 30.14,204.72 ; K5.6 31.26,205.84 ; 54.88,195.99 K9.6 ; K9.6 54.88,198.22 ; K9.6 53.76,197.1 ; K9.6 56,197.1 ; 78.5,188.37 K2.6 ; K2.6 79.62,189.48 ; K2.6 78.5,190.6 ; K2.6 77.38,189.48 ; K4.7 43.96,213.46 ; K4.7 45.08,212.34 ; K4.7 43.96,211.23 ; K4.7 42.84,212.34 ; 67.58,211.23 K7.7 ; K7.7 68.7,212.34 ; K7.7 66.46,212.34 ; K7.7 67.58,213.46 ; 54.88,211.23 K7.6 ; K7.6 56,212.34 ; K7.6 53.76,212.34 ; K7.6 54.88,213.46 ; K13.6 103.24,204.72 ; K13.6 101.01,204.72 ; K13.6 102.12,205.84 ; K13.6 102.12,203.61 ; K14.7 91.2,213.46 ; K14.7 91.2,211.23 ; K14.7 90.08,212.34 ; K14.7 92.32,212.34 ; 91.2,195.99 K10.7 ; K10.7 91.2,198.22 ; K10.7 90.08,197.1 ; K10.7 92.32,197.1 ; 43.96,234.09 K25.7 ; K25.7 43.96,236.32 ; K25.7 42.84,235.2 ; K25.7 45.08,235.2 ; K3.7 67.58,190.6 ; K3.7 66.46,189.48 ; K3.7 67.58,188.37 ; K3.7 68.7,189.48 ; 66.46,197.1 K9.7 ; K9.7 67.58,198.22 ; K9.7 67.58,195.99 ; K9.7 68.7,197.1 ; 91.2,188.37 K2.7 ; K2.7 92.32,189.48 ; K2.7 90.08,189.48 ; K2.7 91.2,190.6 ; 114.82,241.71 K32.7 ; K32.7 113.71,242.82 ; K32.7 115.94,242.82 ; 91.2,218.85 K19.7 ; K19.7 91.2,221.08 ; K19.7 90.08,219.96 ; K19.7 92.32,219.96 ; 66.46,242.82 K30.7 ; K30.7 68.7,242.82 ; K30.7 67.58,241.71 ; 77.38,235.2 K27.6 ; K27.6 78.5,234.09 ; K27.6 78.5,236.32 ; K27.6 79.62,235.2 ; K12.6 79.62,204.72 ; K12.6 78.5,205.84 ; K12.6 77.38,204.72 ; K12.6 78.5,203.61 ; 53.76,204.72 K8.6 ; K8.6 54.88,203.61 ; K8.6 56,204.72 ; K8.6 54.88,205.84 ; 54.88,234.09 K26.6 ; K26.6 56,235.2 ; K26.6 54.88,236.32 ; K26.6 53.76,235.2 ; 77.38,242.82 K31.6 ; K31.6 78.5,241.71 ; K31.6 79.62,242.82 ; 42.84,219.96 K17.7 ; K17.7 43.96,221.08 ; K17.7 45.08,219.96 ; K17.7 43.96,218.85 ; K3.6 54.88,190.6 ; K3.6 53.76,189.48 ; K3.6 54.88,188.37 ; K3.6 56,189.48 ; K22.7 68.7,227.58 ; K22.7 66.46,227.58 ; K22.7 67.58,226.47 ; K22.7 67.58,228.7 ; 77.38,197.1 K10.6 ; K10.6 78.5,198.22 ; K10.6 78.5,195.99 ; K10.6 79.62,197.1 ; 90.08,242.82 K31.7 ; K31.7 91.2,241.71 ; K31.7 92.32,242.82 ; K4.6 32.38,212.34 ; K4.6 31.26,213.46 ; K4.6 31.26,211.23 ; K4.6 30.14,212.34 ; 30.14,242.82 K29.6 ; K29.6 31.26,241.71 ; K29.6 32.38,242.82 ; 78.5,226.47 K23.6 ; K23.6 78.5,228.7 ; K23.6 77.38,227.58 ; K23.6 79.62,227.58 ; 42.84,242.82 K29.7 ; K29.7 43.96,241.71 ; K29.7 45.08,242.82 ; K13.7 114.82,205.84 ; K13.7 115.94,204.72 ; K13.7 113.71,204.72 ; K13.7 114.82,203.61 ; K21.6 32.38,227.58 ; K21.6 30.14,227.58 ; K21.6 31.26,228.7 ; K21.6 31.26,226.47 ; 114.82,234.09 K28.7 ; K28.7 115.94,235.2 ; K28.7 114.82,236.32 ; K28.7 113.71,235.2 ; K26.7 68.7,235.2 ; K26.7 67.58,236.32 ; K26.7 66.46,235.2 ; K26.7 67.58,234.09
  L21_DGND w0.203: K17.7 43.96,221.08 ; K17.7 42.84,219.96 ; K17.7 45.08,219.96 ; K17.7 43.96,218.85 ; K8.7 67.58,205.84 ; K8.7 67.58,203.61 ; K8.7 68.7,204.72 ; K8.7 66.46,204.72 ; 42.84,189.48 K16.7 ; K16.7 43.96,188.37 ; K16.7 45.08,189.48 ; K16.7 43.96,190.6 ; 54.88,211.23 K7.6 ; K7.6 53.76,212.34 ; K7.6 56,212.34 ; K7.6 54.88,213.46 ; K4.6 31.26,213.46 ; K4.6 31.26,211.23 ; K4.6 30.14,212.34 ; K4.6 32.38,212.34 ; 53.76,204.72 K8.6 ; K8.6 54.88,205.84 ; K8.6 56,204.72 ; K8.6 54.88,203.61 ; 31.26,188.37 K16.6 ; K16.6 32.38,189.48 ; K16.6 31.26,190.6 ; K16.6 30.14,189.48 ; 77.38,227.58 K23.6 ; K23.6 78.5,226.47 ; K23.6 78.5,228.7 ; K23.6 79.62,227.58 ; K10.7 91.2,198.22 ; K10.7 91.2,195.99 ; K10.7 92.32,197.1 ; K10.7 90.08,197.1 ; K21.7 43.96,228.7 ; K21.7 45.08,227.58 ; K21.7 42.84,227.58 ; K21.7 43.96,226.47 ; K25.6 32.38,235.2 ; K25.6 31.26,234.09 ; K25.6 30.14,235.2 ; K25.6 31.26,236.32 ; K22.6 54.88,228.7 ; K22.6 56,227.58 ; K22.6 54.88,226.47 ; K22.6 53.76,227.58 ; K11.6 102.12,198.22 ; K11.6 102.12,195.99 ; K11.6 101.01,197.1 ; K11.6 103.24,197.1 ; K31.7 92.32,242.82 ; K31.7 90.08,242.82 ; K31.7 91.2,241.71 ; K2.7 92.32,189.48 ; K2.7 91.2,190.6 ; K2.7 91.2,188.37 ; K2.7 90.08,189.48 ; 114.82,218.85 K20.7 ; K20.7 114.82,221.08 ; K20.7 115.94,219.96 ; K20.7 113.71,219.96 ; K3.6 54.88,190.6 ; K3.6 54.88,188.37 ; K3.6 53.76,189.48 ; K3.6 56,189.48 ; 78.5,188.37 K2.6 ; K2.6 77.38,189.48 ; K2.6 79.62,189.48 ; K2.6 78.5,190.6 ; 114.82,234.09 K28.7 ; K28.7 113.71,235.2 ; K28.7 114.82,236.32 ; K28.7 115.94,235.2 ; 67.58,226.47 K22.7 ; K22.7 68.7,227.58 ; K22.7 67.58,228.7 ; K22.7 66.46,227.58 ; K26.6 56,235.2 ; K26.6 54.88,234.09 ; K26.6 53.76,235.2 ; K26.6 54.88,236.32 ; 30.14,242.82 K29.6 ; K29.6 32.38,242.82 ; K29.6 31.26,241.71 ; K18.6 54.88,221.08 ; K18.6 56,219.96 ; K18.6 54.88,218.85 ; K18.6 53.76,219.96 ; K31.6 79.62,242.82 ; K31.6 78.5,241.71 ; K31.6 77.38,242.82 ; K3.7 67.58,190.6 ; K3.7 68.7,189.48 ; K3.7 67.58,188.37 ; K3.7 66.46,189.48 ; 90.08,235.2 K27.7 ; K27.7 92.32,235.2 ; K27.7 91.2,234.09 ; K27.7 91.2,236.32 ; 67.58,241.71 K30.7 ; K30.7 68.7,242.82 ; K30.7 66.46,242.82 ; K17.6 32.38,219.96 ; K17.6 31.26,218.85 ; K17.6 30.14,219.96 ; K17.6 31.26,221.08 ; 113.71,204.72 K13.7 ; K13.7 114.82,203.61 ; K13.7 114.82,205.84 ; K13.7 115.94,204.72 ; K7.7 68.7,212.34 ; K7.7 67.58,213.46 ; K7.7 67.58,211.23 ; K7.7 66.46,212.34 ; K9.6 56,197.1 ; K9.6 54.88,198.22 ; K9.6 54.88,195.99 ; K9.6 53.76,197.1 ; K6.6 32.38,197.1 ; K6.6 31.26,198.22 ; K6.6 31.26,195.99 ; K6.6 30.14,197.1 ; 114.82,188.37 K1.7 ; K1.7 114.82,190.6 ; K1.7 115.94,189.48 ; K1.7 113.71,189.48 ; 54.88,241.71 K30.6 ; K30.6 53.76,242.82 ; K30.6 56,242.82 ; K12.7 92.32,204.72 ; K12.7 91.2,205.84 ; K12.7 91.2,203.61 ; K12.7 90.08,204.72 ; 43.96,203.61 K5.7 ; K5.7 43.96,205.84 ; K5.7 45.08,204.72 ; K5.7 42.84,204.72 ; 101.01,227.58 K24.6 ; K24.6 103.24,227.58 ; K24.6 102.12,228.7 ; K24.6 102.12,226.47 ; 31.26,203.61 K5.6 ; K5.6 32.38,204.72 ; K5.6 30.14,204.72 ; K5.6 31.26,205.84 ; K21.6 32.38,227.58 ; K21.6 30.14,227.58 ; K21.6 31.26,226.47 ; K21.6 31.26,228.7 ; 101.01,204.72 K13.6 ; K13.6 102.12,205.84 ; K13.6 103.24,204.72 ; K13.6 102.12,203.61 ; K19.6 79.62,219.96 ; K19.6 78.5,218.85 ; K19.6 78.5,221.08 ; K19.6 77.38,219.96 ; K26.7 67.58,236.32 ; K26.7 68.7,235.2 ; K26.7 67.58,234.09 ; K26.7 66.46,235.2 ; K25.7 45.08,235.2 ; K25.7 43.96,236.32 ; K25.7 42.84,235.2 ; K25.7 43.96,234.09 ; K9.7 67.58,198.22 ; K9.7 68.7,197.1 ; K9.7 67.58,195.99 ; K9.7 66.46,197.1 ; 90.08,227.58 K23.7 ; K23.7 91.2,228.7 ; K23.7 91.2,226.47 ; K23.7 92.32,227.58 ; 78.5,234.09 K27.6 ; K27.6 77.38,235.2 ; K27.6 78.5,236.32 ; K27.6 79.62,235.2 ; 113.71,197.1 K11.7 ; K11.7 114.82,198.22 ; K11.7 114.82,195.99 ; K11.7 115.94,197.1 ; 66.46,219.96 K18.7 ; K18.7 67.58,218.85 ; K18.7 68.7,219.96 ; K18.7 67.58,221.08 ; 77.38,204.72 K12.6 ; K12.6 78.5,203.61 ; K12.6 78.5,205.84 ; K12.6 79.62,204.72 ; 102.12,234.09 K28.6 ; K28.6 103.24,235.2 ; K28.6 101.01,235.2 ; K28.6 102.12,236.32 ; K14.6 79.62,212.34 ; K14.6 77.38,212.34 ; K14.6 78.5,213.46 ; K14.6 78.5,211.23 ; K6.7 45.08,197.1 ; K6.7 43.96,198.22 ; K6.7 42.84,197.1 ; K6.7 43.96,195.99 ; K15.6 102.12,213.46 ; K15.6 103.24,212.34 ; K15.6 101.01,212.34 ; K15.6 102.12,211.23 ; K24.7 114.82,228.7 ; K24.7 113.71,227.58 ; K24.7 114.82,226.47 ; K24.7 115.94,227.58 ; 90.08,219.96 K19.7 ; K19.7 92.32,219.96 ; K19.7 91.2,221.08 ; K19.7 91.2,218.85 ; 102.12,218.85 K20.6 ; K20.6 103.24,219.96 ; K20.6 102.12,221.08 ; K20.6 101.01,219.96 ; K29.7 45.08,242.82 ; K29.7 42.84,242.82 ; K29.7 43.96,241.71 ; K15.7 115.94,212.34 ; K15.7 114.82,213.46 ; K15.7 113.71,212.34 ; K15.7 114.82,211.23 ; K14.7 91.2,213.46 ; K14.7 90.08,212.34 ; K14.7 91.2,211.23 ; K14.7 92.32,212.34 ; 77.38,197.1 K10.6 ; K10.6 78.5,198.22 ; K10.6 79.62,197.1 ; K10.6 78.5,195.99 ; K32.6 103.24,242.82 ; K32.6 101.01,242.82 ; K32.6 102.12,241.71 ; 102.12,188.37 K1.6 ; K1.6 103.24,189.48 ; K1.6 102.12,190.6 ; K1.6 101.01,189.48 ; 114.82,241.71 K32.7 ; K32.7 115.94,242.82 ; K32.7 113.71,242.82 ; 42.84,212.34 K4.7 ; K4.7 43.96,213.46 ; K4.7 43.96,211.23 ; K4.7 45.08,212.34
  L23_DGND w0.203: 90.08,212.34 K14.7 ; K14.7 91.2,211.23 ; K14.7 91.2,213.46 ; K14.7 92.32,212.34 ; 30.14,235.2 K25.6 ; K25.6 31.26,234.09 ; K25.6 31.26,236.32 ; K25.6 32.38,235.2 ; 90.08,219.96 K19.7 ; K19.7 92.32,219.96 ; K19.7 91.2,221.08 ; K19.7 91.2,218.85 ; 102.12,218.85 K20.6 ; K20.6 103.24,219.96 ; K20.6 101.01,219.96 ; K20.6 102.12,221.08 ; 66.46,197.1 K9.7 ; K9.7 67.58,198.22 ; K9.7 68.7,197.1 ; K9.7 67.58,195.99 ; 53.76,242.82 K30.6 ; K30.6 54.88,241.71 ; K30.6 54.88,243.94 ; K30.6 56,242.82 ; K24.6 102.12,228.7 ; K24.6 102.12,226.47 ; K24.6 103.24,227.58 ; K24.6 101.01,227.58 ; K30.7 68.7,242.82 ; K30.7 67.58,243.94 ; K30.7 66.46,242.82 ; K30.7 67.58,241.71 ; 78.5,203.61 K12.6 ; K12.6 78.5,205.84 ; K12.6 79.62,204.72 ; K12.6 77.38,204.72 ; K23.6 78.5,228.7 ; K23.6 77.38,227.58 ; K23.6 78.5,226.47 ; K23.6 79.62,227.58 ; K13.6 103.24,204.72 ; K13.6 101.01,204.72 ; K13.6 102.12,203.61 ; K13.6 102.12,205.84 ; 30.14,204.72 K5.6 ; K5.6 31.26,205.84 ; K5.6 32.38,204.72 ; K5.6 31.26,203.61 ; 30.14,212.34 K4.6 ; K4.6 31.26,213.46 ; K4.6 32.38,212.34 ; K4.6 31.26,211.23 ; 67.58,218.85 K18.7 ; K18.7 68.7,219.96 ; K18.7 66.46,219.96 ; K18.7 67.58,221.08 ; 91.2,188.37 K2.7 ; K2.7 90.08,189.48 ; K2.7 91.2,190.6 ; K2.7 92.32,189.48 ; K7.6 54.88,213.46 ; K7.6 56,212.34 ; K7.6 54.88,211.23 ; K7.6 53.76,212.34 ; 77.38,197.1 K10.6 ; K10.6 79.62,197.1 ; K10.6 78.5,195.99 ; K10.6 78.5,198.22 ; 78.5,218.85 K19.6 ; K19.6 77.38,219.96 ; K19.6 79.62,219.96 ; K19.6 78.5,221.08 ; 54.88,203.61 K8.6 ; K8.6 54.88,205.84 ; K8.6 53.76,204.72 ; K8.6 56,204.72 ; K16.7 43.96,190.6 ; K16.7 45.08,189.48 ; K16.7 42.84,189.48 ; K16.7 43.96,188.37 ; K31.7 91.2,243.94 ; K31.7 91.2,241.71 ; K31.7 92.32,242.82 ; K31.7 90.08,242.82 ; K4.7 43.96,213.46 ; K4.7 42.84,212.34 ; K4.7 43.96,211.23 ; K4.7 45.08,212.34 ; K3.7 67.58,190.6 ; K3.7 66.46,189.48 ; K3.7 68.7,189.48 ; K3.7 67.58,188.37 ; 77.38,189.48 K2.6 ; K2.6 78.5,188.37 ; K2.6 79.62,189.48 ; K2.6 78.5,190.6 ; 53.76,219.96 K18.6 ; K18.6 54.88,218.85 ; K18.6 56,219.96 ; K18.6 54.88,221.08 ; 101.01,235.2 K28.6 ; K28.6 103.24,235.2 ; K28.6 102.12,236.32 ; K28.6 102.12,234.09 ; K6.7 45.08,197.1 ; K6.7 42.84,197.1 ; K6.7 43.96,195.99 ; K6.7 43.96,198.22 ; K6.6 32.38,197.1 ; K6.6 31.26,198.22 ; K6.6 31.26,195.99 ; K6.6 30.14,197.1 ; K26.7 67.58,236.32 ; K26.7 67.58,234.09 ; K26.7 68.7,235.2 ; K26.7 66.46,235.2 ; K21.6 31.26,228.7 ; K21.6 32.38,227.58 ; K21.6 30.14,227.58 ; K21.6 31.26,226.47 ; K14.6 78.5,213.46 ; K14.6 77.38,212.34 ; K14.6 78.5,211.23 ; K14.6 79.62,212.34 ; K21.7 45.08,227.58 ; K21.7 42.84,227.58 ; K21.7 43.96,226.47 ; K21.7 43.96,228.7 ; 31.26,188.37 K16.6 ; K16.6 30.14,189.48 ; K16.6 31.26,190.6 ; K16.6 32.38,189.48 ; K31.6 79.62,242.82 ; K31.6 77.38,242.82 ; K31.6 78.5,243.94 ; K31.6 78.5,241.71 ; 53.76,189.48 K3.6 ; K3.6 54.88,188.37 ; K3.6 56,189.48 ; K3.6 54.88,190.6 ; K29.7 45.08,242.82 ; K29.7 43.96,243.94 ; K29.7 42.84,242.82 ; K29.7 43.96,241.71 ; 67.58,226.47 K22.7 ; K22.7 67.58,228.7 ; K22.7 68.7,227.58 ; K22.7 66.46,227.58 ; K26.6 56,235.2 ; K26.6 53.76,235.2 ; K26.6 54.88,234.09 ; K26.6 54.88,236.32 ; 101.01,242.82 K32.6 ; K32.6 102.12,243.94 ; K32.6 102.12,241.71 ; K32.6 103.24,242.82 ; K9.6 54.88,198.22 ; K9.6 53.76,197.1 ; K9.6 54.88,195.99 ; K9.6 56,197.1 ; K10.7 92.32,197.1 ; K10.7 90.08,197.1 ; K10.7 91.2,198.22 ; K10.7 91.2,195.99 ; 90.08,204.72 K12.7 ; K12.7 91.2,203.61 ; K12.7 92.32,204.72 ; K12.7 91.2,205.84 ; 101.01,212.34 K15.6 ; K15.6 103.24,212.34 ; K15.6 102.12,211.23 ; K15.6 102.12,213.46 ; K11.6 103.24,197.1 ; K11.6 102.12,195.99 ; K11.6 101.01,197.1 ; K11.6 102.12,198.22 ; 54.88,226.47 K22.6 ; K22.6 56,227.58 ; K22.6 54.88,228.7 ; K22.6 53.76,227.58 ; K1.6 103.24,189.48 ; K1.6 101.01,189.48 ; K1.6 102.12,190.6 ; K1.6 102.12,188.37 ; 90.08,227.58 K23.7 ; K23.7 91.2,226.47 ; K23.7 92.32,227.58 ; K23.7 91.2,228.7 ; K8.7 68.7,204.72 ; K8.7 67.58,205.84 ; K8.7 67.58,203.61 ; K8.7 66.46,204.72 ; K27.6 79.62,235.2 ; K27.6 77.38,235.2 ; K27.6 78.5,236.32 ; K27.6 78.5,234.09 ; K17.6 31.26,221.08 ; K17.6 31.26,218.85 ; K17.6 32.38,219.96 ; K17.6 30.14,219.96 ; 30.14,242.82 K29.6 ; K29.6 31.26,241.71 ; K29.6 32.38,242.82 ; K29.6 31.26,243.94 ; K17.7 45.08,219.96 ; K17.7 43.96,218.85 ; K17.7 43.96,221.08 ; K17.7 42.84,219.96 ; K27.7 92.32,235.2 ; K27.7 91.2,234.09 ; K27.7 91.2,236.32 ; K27.7 90.08,235.2 ; K7.7 68.7,212.34 ; K7.7 67.58,211.23 ; K7.7 67.58,213.46 ; K7.7 66.46,212.34 ; 43.96,234.09 K25.7 ; K25.7 43.96,236.32 ; K25.7 42.84,235.2 ; K25.7 45.08,235.2 ; K5.7 45.08,204.72 ; K5.7 43.96,205.84 ; K5.7 43.96,203.61 ; K5.7 42.84,204.72
  L25_DGND w0.203: 77.38,197.1 K10.6 ; K10.6 78.5,195.99 ; K10.6 78.5,198.22 ; K10.6 79.62,197.1 ; 67.58,226.47 K22.7 ; K22.7 67.58,228.7 ; K22.7 66.46,227.58 ; K22.7 68.7,227.58 ; K5.7 43.96,205.84 ; K5.7 42.84,204.72 ; K5.7 45.08,204.72 ; K5.7 43.96,203.61 ; 30.14,212.34 K4.6 ; K4.6 32.38,212.34 ; K4.6 31.26,211.23 ; K4.6 31.26,213.46 ; 31.26,195.99 K6.6 ; K6.6 31.26,198.22 ; K6.6 30.14,197.1 ; K6.6 32.38,197.1 ; K31.7 91.2,243.94 ; K31.7 92.32,242.82 ; K31.7 91.2,241.71 ; K31.7 90.08,242.82 ; K19.7 92.32,219.96 ; K19.7 91.2,218.85 ; K19.7 90.08,219.96 ; K19.7 91.2,221.08 ; K24.6 103.24,227.58 ; K24.6 102.12,228.7 ; K24.6 102.12,226.47 ; K24.6 101.01,227.58 ; K4.7 45.08,212.34 ; K4.7 43.96,213.46 ; K4.7 42.84,212.34 ; K4.7 43.96,211.23 ; K5.6 31.26,205.84 ; K5.6 31.26,203.61 ; K5.6 30.14,204.72 ; K5.6 32.38,204.72 ; K18.7 68.7,219.96 ; K18.7 67.58,218.85 ; K18.7 66.46,219.96 ; K18.7 67.58,221.08 ; 91.2,226.47 K23.7 ; K23.7 90.08,227.58 ; K23.7 91.2,228.7 ; K23.7 92.32,227.58 ; 31.26,241.71 K29.6 ; K29.6 32.38,242.82 ; K29.6 31.26,243.94 ; K29.6 30.14,242.82 ; K29.7 43.96,243.94 ; K29.7 43.96,241.71 ; K29.7 45.08,242.82 ; K29.7 42.84,242.82 ; 102.12,218.85 K20.6 ; K20.6 101.01,219.96 ; K20.6 102.12,221.08 ; K20.6 103.24,219.96 ; K17.6 32.38,219.96 ; K17.6 31.26,218.85 ; K17.6 31.26,221.08 ; K17.6 30.14,219.96 ; 67.58,203.61 K8.7 ; K8.7 67.58,205.84 ; K8.7 66.46,204.72 ; K8.7 68.7,204.72 ; K6.7 45.08,197.1 ; K6.7 42.84,197.1 ; K6.7 43.96,198.22 ; K6.7 43.96,195.99 ; 91.2,234.09 K27.7 ; K27.7 92.32,235.2 ; K27.7 91.2,236.32 ; K27.7 90.08,235.2 ; K9.7 67.58,198.22 ; K9.7 68.7,197.1 ; K9.7 66.46,197.1 ; K9.7 67.58,195.99 ; 54.88,188.37 K3.6 ; K3.6 54.88,190.6 ; K3.6 56,189.48 ; K3.6 53.76,189.48 ; 66.46,212.34 K7.7 ; K7.7 68.7,212.34 ; K7.7 67.58,213.46 ; K7.7 67.58,211.23 ; K25.7 45.08,235.2 ; K25.7 43.96,236.32 ; K25.7 42.84,235.2 ; K25.7 43.96,234.09 ; 53.76,204.72 K8.6 ; K8.6 54.88,205.84 ; K8.6 56,204.72 ; K8.6 54.88,203.61 ; K26.7 67.58,236.32 ; K26.7 67.58,234.09 ; K26.7 68.7,235.2 ; K26.7 66.46,235.2 ; 54.88,218.85 K18.6 ; K18.6 56,219.96 ; K18.6 53.76,219.96 ; K18.6 54.88,221.08 ; 43.96,226.47 K21.7 ; K21.7 42.84,227.58 ; K21.7 43.96,228.7 ; K21.7 45.08,227.58 ; 42.84,189.48 K16.7 ; K16.7 43.96,190.6 ; K16.7 45.08,189.48 ; K16.7 43.96,188.37 ; 102.12,195.99 K11.6 ; K11.6 101.01,197.1 ; K11.6 103.24,197.1 ; K11.6 102.12,198.22 ; 78.5,203.61 K12.6 ; K12.6 77.38,204.72 ; K12.6 79.62,204.72 ; K12.6 78.5,205.84 ; 30.14,235.2 K25.6 ; K25.6 31.26,236.32 ; K25.6 31.26,234.09 ; K25.6 32.38,235.2 ; K2.6 79.62,189.48 ; K2.6 77.38,189.48 ; K2.6 78.5,188.37 ; K2.6 78.5,190.6 ; K26.6 54.88,236.32 ; K26.6 54.88,234.09 ; K26.6 53.76,235.2 ; K26.6 56,235.2 ; K1.6 102.12,190.6 ; K1.6 101.01,189.48 ; K1.6 103.24,189.48 ; K1.6 102.12,188.37 ; 77.38,235.2 K27.6 ; K27.6 78.5,234.09 ; K27.6 79.62,235.2 ; K27.6 78.5,236.32 ; 67.58,241.71 K30.7 ; K30.7 66.46,242.82 ; K30.7 68.7,242.82 ; K30.7 67.58,243.94 ; 101.01,212.34 K15.6 ; K15.6 102.12,211.23 ; K15.6 103.24,212.34 ; K15.6 102.12,213.46 ; 77.38,219.96 K19.6 ; K19.6 79.62,219.96 ; K19.6 78.5,218.85 ; K19.6 78.5,221.08 ; 91.2,203.61 K12.7 ; K12.7 92.32,204.72 ; K12.7 90.08,204.72 ; K12.7 91.2,205.84 ; 66.46,189.48 K3.7 ; K3.7 67.58,190.6 ; K3.7 67.58,188.37 ; K3.7 68.7,189.48 ; 90.08,197.1 K10.7 ; K10.7 91.2,198.22 ; K10.7 92.32,197.1 ; K10.7 91.2,195.99 ; K14.7 92.32,212.34 ; K14.7 91.2,211.23 ; K14.7 91.2,213.46 ; K14.7 90.08,212.34 ; 78.5,226.47 K23.6 ; K23.6 78.5,228.7 ; K23.6 77.38,227.58 ; K23.6 79.62,227.58 ; 78.5,211.23 K14.6 ; K14.6 77.38,212.34 ; K14.6 79.62,212.34 ; K14.6 78.5,213.46 ; 31.26,188.37 K16.6 ; K16.6 30.14,189.48 ; K16.6 31.26,190.6 ; K16.6 32.38,189.48 ; K13.6 102.12,205.84 ; K13.6 103.24,204.72 ; K13.6 101.01,204.72 ; K13.6 102.12,203.61 ; 43.96,218.85 K17.7 ; K17.7 43.96,221.08 ; K17.7 42.84,219.96 ; K17.7 45.08,219.96 ; 102.12,241.71 K32.6 ; K32.6 103.24,242.82 ; K32.6 102.12,243.94 ; K32.6 101.01,242.82 ; K9.6 54.88,198.22 ; K9.6 53.76,197.1 ; K9.6 56,197.1 ; K9.6 54.88,195.99 ; K21.6 31.26,228.7 ; K21.6 31.26,226.47 ; K21.6 32.38,227.58 ; K21.6 30.14,227.58 ; K2.7 92.32,189.48 ; K2.7 91.2,188.37 ; K2.7 90.08,189.48 ; K2.7 91.2,190.6 ; K22.6 54.88,228.7 ; K22.6 56,227.58 ; K22.6 54.88,226.47 ; K22.6 53.76,227.58 ; K7.6 56,212.34 ; K7.6 54.88,213.46 ; K7.6 54.88,211.23 ; K7.6 53.76,212.34 ; K30.6 54.88,243.94 ; K30.6 53.76,242.82 ; K30.6 54.88,241.71 ; K30.6 56,242.82 ; K28.6 103.24,235.2 ; K28.6 102.12,236.32 ; K28.6 102.12,234.09 ; K28.6 101.01,235.2 ; 77.38,242.82 K31.6 ; K31.6 79.62,242.82 ; K31.6 78.5,241.71 ; K31.6 78.5,243.94
  BOTTOM w0.152: SH10.1 v1(132.52,213.51)
  vias: v1(16.25,173.89) v1(16.25,168.81) v1(16.25,158.65) v1(16.25,153.57) v1(21.33,234.85) v1(21.33,229.77) v1(21.33,224.69) v1(21.33,209.45) v1(21.33,204.37) v1(21.33,199.29) v1(21.33,194.21) v1(21.33,173.89) v1(21.33,168.81) v1(21.33,163.73) v1(21.33,158.65) v1(21.33,153.57) v1(21.33,148.49) v1(24.35,219.2) v1(24.35,216.41) v1(26.41,178.97) v1(26.41,173.89) v1(26.41,168.81) v1(26.41,163.73) v1(26.41,158.65) v1(26.41,153.57) v1(26.41,148.49) v1(26.41,143.41) v1(31.49,178.97) v1(31.49,173.89) v1(31.49,168.81) v1(31.49,163.73) v1(36.57,178.97) v1(36.57,173.89) v1(36.57,168.81) v1(41.65,178.97) v1(41.65,173.89) v1(41.65,168.81) v1(42.18,288.29) v1(42.18,283.21) v1(42.96,279.15) v1(43.75,274.32) v1(43.75,271.53) v1(46.73,178.97) v1(46.73,173.89) v1(46.73,168.81) v1(46.73,163.73) v1(46.73,158.65) v1(46.73,148.49) v1(50.54,279.15) v1(51.32,288.29) v1(51.32,283.21) v1(51.81,178.97) v1(51.81,173.89) v1(51.81,168.81) v1(56.89,178.97) v1(56.89,173.89) v1(56.89,168.81) v1(59.76,250.95) v1(59.76,248.16) v1(61.97,194.21) v1(61.97,178.97) v1(61.97,173.89) v1(61.97,168.81) v1(62.81,269.13) v1(62.81,266.34) v1(67.05,178.97) v1(67.05,173.89) v1(67.05,168.81) v1(67.05,163.73) v1(67.05,158.65) v1(67.05,153.57) v1(67.05,148.49) v1(67.05,143.41) v1(72.13,178.97) v1(72.13,173.89) v1(72.13,168.81) v1(72.13,163.73) v1(77.21,178.97) v1(77.21,173.89) v1(77.21,168.81) v1(82.29,178.97) v1(82.29,173.89) v1(87.37,178.97) v2(139.52,212.63) v2(140.32,212.63) v2(141.12,212.63) v2(141.92,212.63) v2(141.92,211.83) v2(142.72,210.23) v2(142.72,209.43) v2(142.72,208.63) v2(145.75,211.84) v2(145.92,212.63)
